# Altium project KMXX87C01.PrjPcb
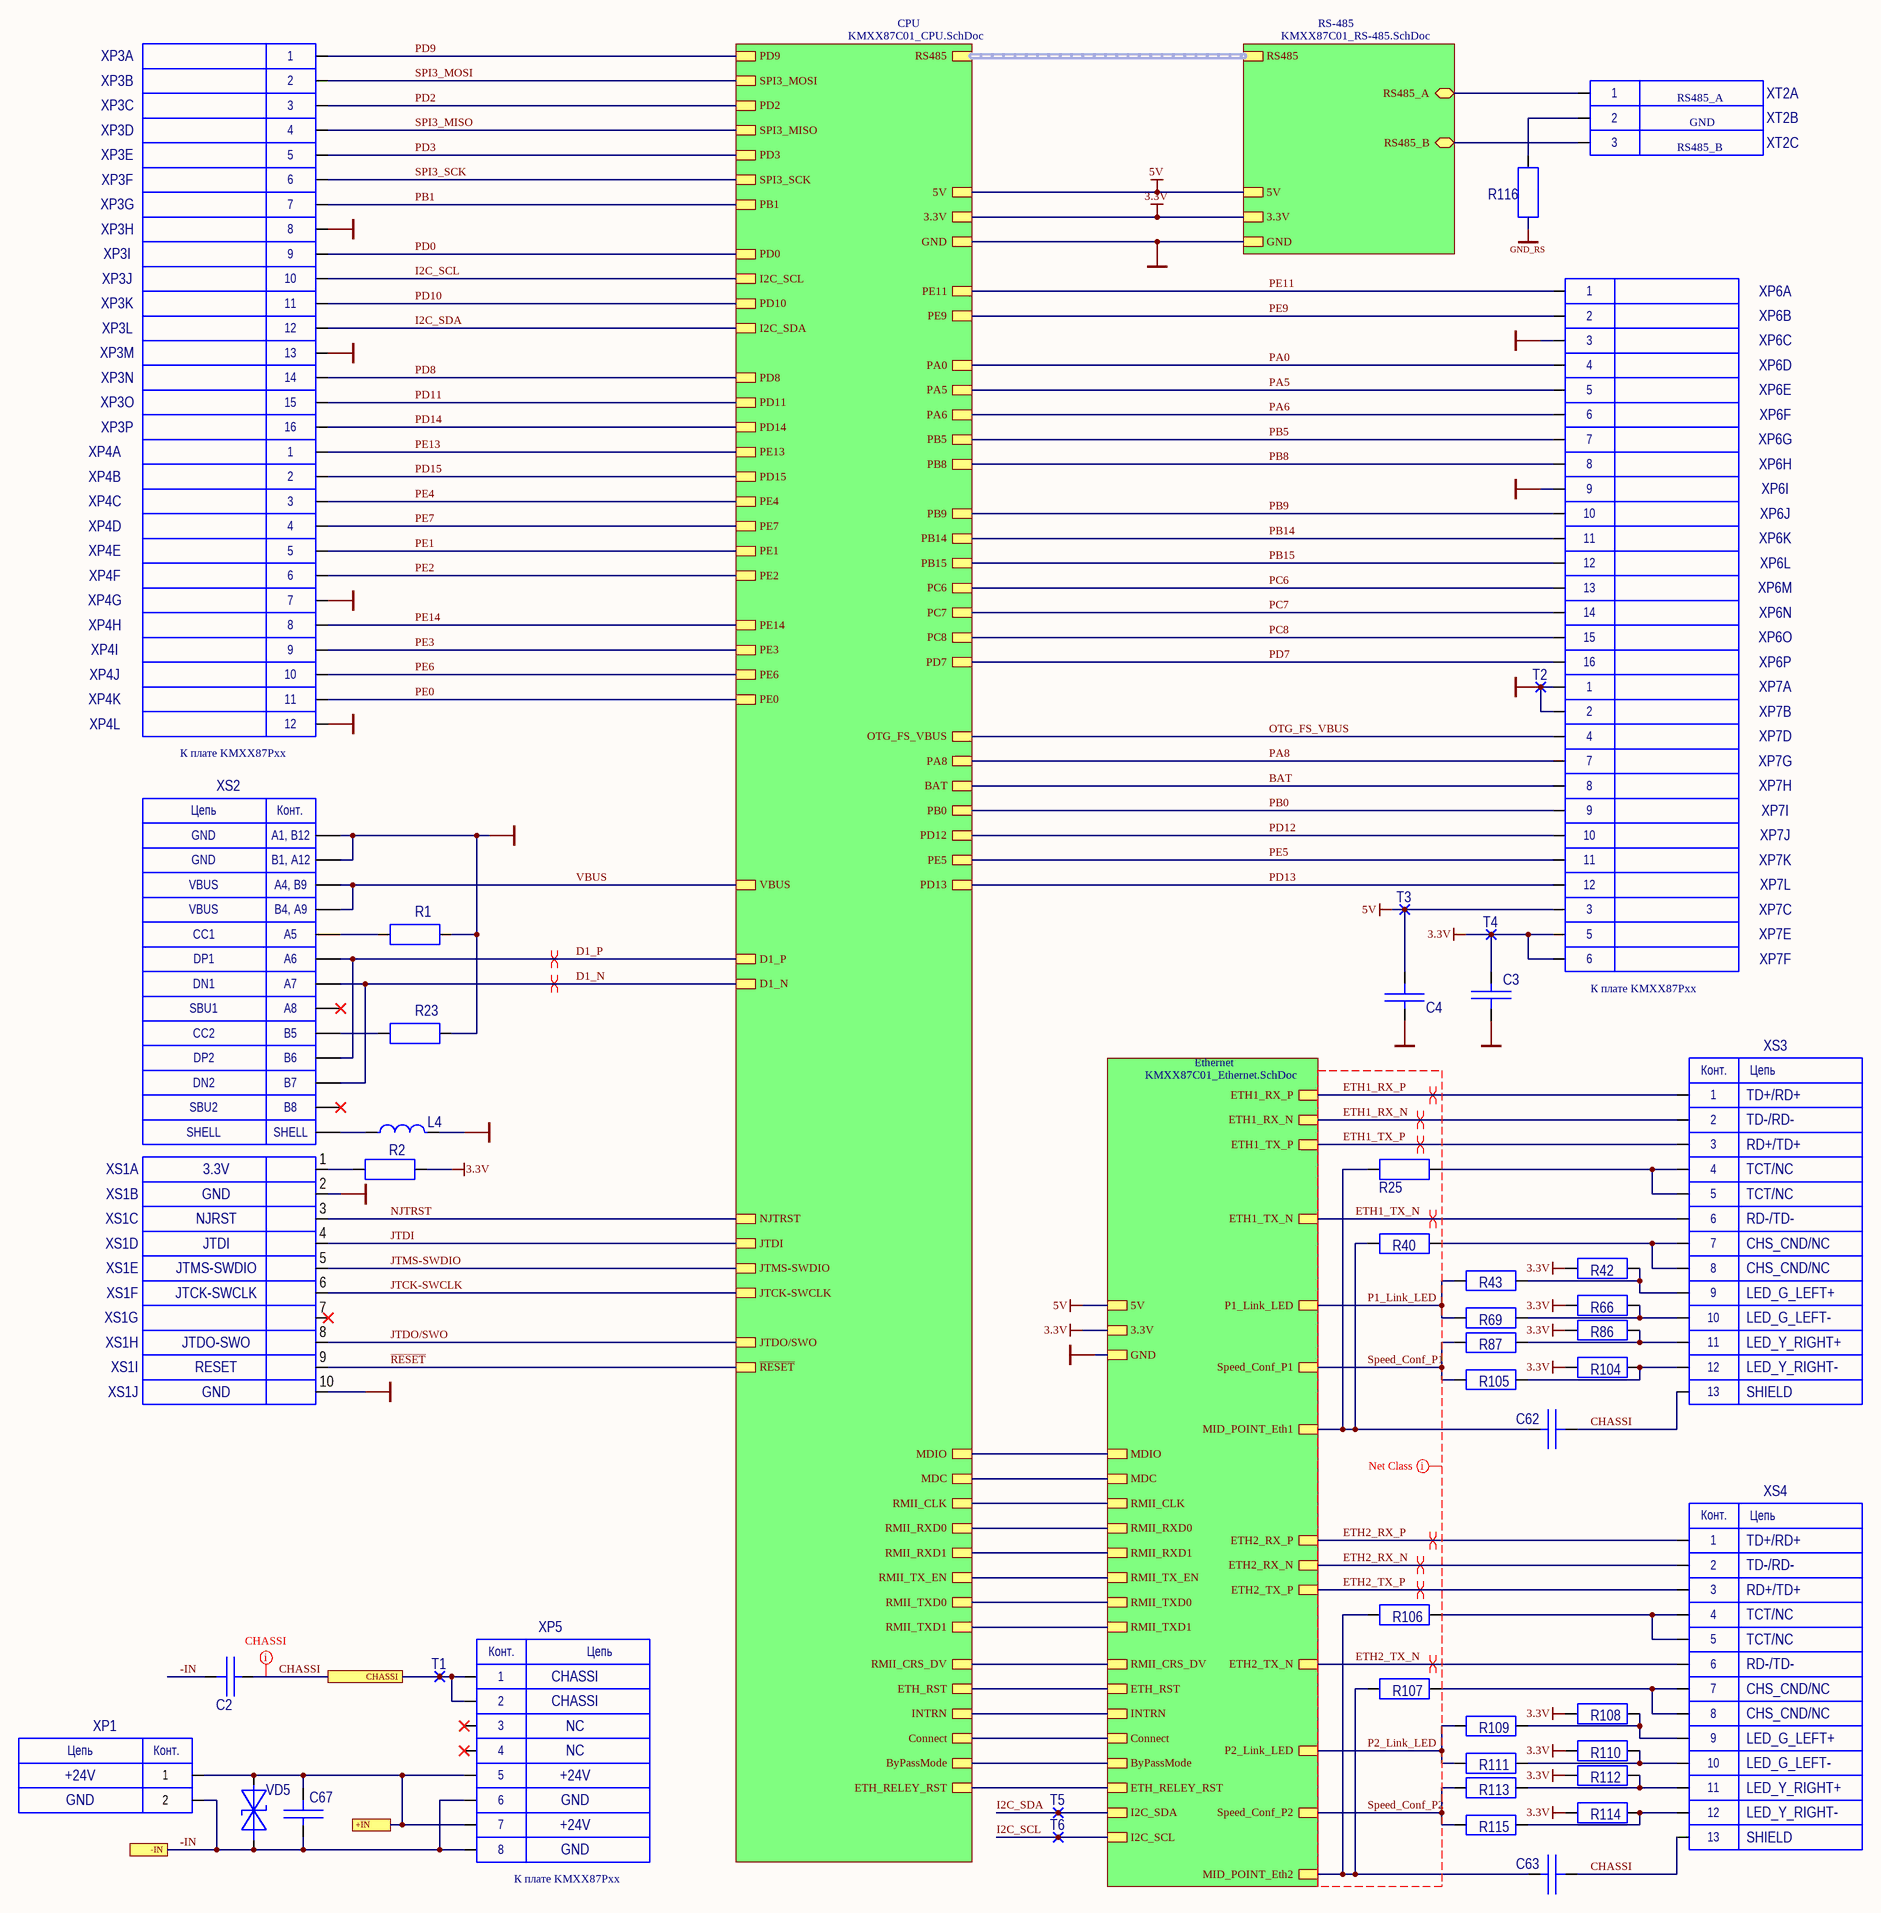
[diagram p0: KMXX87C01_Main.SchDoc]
4 sheets, 291 parts. Net scope: hierarchical (ports join the sheet entries above them; power ports are global).
Board file: KMXX87C01.PcbDoc
Sheets:
  KMXX87C01_Main.SchDoc
    CPU = KMXX87C01_CPU.SchDoc
    RS-485 = KMXX87C01_RS-485.SchDoc
    Ethernet = KMXX87C01_Ethernet.SchDoc

## Sheet KMXX87C01_Main.SchDoc
size 594 x 420 mm; SheetNumber: 1; SheetTotal: 4; Mass: not use; Title2: Схема электрическая принципиальная

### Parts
C2  CS-JY-Y2-1000пФ-20%-Y5U (Murata, 7.0x5.0x7.5)  [JY_8-A2]  (value not drawn)
C3  C0402-16В-0,1мкФ-10%-X7R (Walsin, 0402B104K160CT)  [C0402]  (value not drawn)
C4  C0402-16В-0,1мкФ-10%-X7R (Walsin, 0402B104K160CT)  [C0402]  (value not drawn)
C62  C1206-2000B-1000пФ-10%-X7R (Walsin, 1206B102K202CT  [CC1206-KL]  (value not drawn)
C63  C1206-2000B-1000пФ-10%-X7R (Walsin, 1206B102K202CT  [CC1206-KL]  (value not drawn)
C67  C1206-100В-0,1мкФ-10%-X7R (Samsung, CL31B104KCFNNN  [CC1206-KL]  (value not drawn)
L4  FB0805-5А-120 Ом (100МГц)-25%-0,02 Ом (INPAQ, MHC2012S121UBP)  [L0805]  (value not drawn)
R1  RC03-5,1кОм 1%  [RC0603-KL]  (value not drawn)
R2  RC02-0,0 Ом 5%  [R0402]  (value not drawn)
R23  RC03-5,1кОм 1%  [RC0603-KL]  (value not drawn)
R25  RC03-75 Ом 5%  [RC0603-KL]  (value not drawn)
R40  RC03-75 Ом 5%  [RC0603-KL]  (value not drawn)
R42  RC02-470 Ом 1%  [R0402]  (value not drawn)
R43  RC02-0,0 Ом 5%  [R0402]  (value not drawn)
R66  RC02-470 Ом 1%  [R0402]  (value not drawn)
R69  RC02-0,0 Ом 5%  [R0402]  (value not drawn)
R86  RC02-470 Ом 1%  [R0402]  (value not drawn)
R87  RC02-0,0 Ом 5%  [R0402]  (value not drawn)
R104  RC02-470 Ом 1%  [R0402]  (value not drawn)
R105  RC02-0,0 Ом 5%  [R0402]  (value not drawn)
R106  RC03-75 Ом 5%  [RC0603-KL]  (value not drawn)
R107  RC03-75 Ом 5%  [RC0603-KL]  (value not drawn)
R108  RC02-470 Ом 1%  [R0402]  (value not drawn)
R109  RC02-0,0 Ом 5%  [R0402]  (value not drawn)
R110  RC02-470 Ом 1%  [R0402]  (value not drawn)
R111  RC02-0,0 Ом 5%  [R0402]  (value not drawn)
R112  RC02-470 Ом 1%  [R0402]  (value not drawn)
R113  RC02-0,0 Ом 5%  [R0402]  (value not drawn)
R114  RC02-470 Ом 1%  [R0402]  (value not drawn)
R115  RC02-0,0 Ом 5%  [R0402]  (value not drawn)
R116  RC06-100 Ом 5%  [RC1206-KL]  (value not drawn)
T1  *  [T17A]  (value not drawn)  (no BOM)
T2  *  [T07A]  (value not drawn)  (no BOM)
T3  *  [T07A]  (value not drawn)  (no BOM)
T4  *  [T07A]  (value not drawn)  (no BOM)
T5  *  [T07A]  (value not drawn)  (no BOM)
T6  *  [T07A]  (value not drawn)  (no BOM)
VD5  SMBJ48CA-TR (STM, DO-214AA(SMB))  [SMB(DO-214AA)]  (value not drawn)
XP1  *  [2EDGR-5.08-02P]  (value not drawn)
XP3  PLD2-2 (Connfly,  DS1025-05-2*40P8BV1-B) (16 контактов)  [PLD2-16]  (value not drawn)  (parts A,B,C,D,E,F,G,H,I,J,K,L,M,N,O,P of 16)
XP4  *  [PLD2-12]  (value not drawn)  (parts A,B,C,D,E,F,G,H,I,J,K,L of 12)
XP5  *  [PLD2-08]  (value not drawn)
XP6  PLD2-2 (Connfly,  DS1025-05-2*40P8BV1-B) (16 контактов)  [PLD2-16]  (value not drawn)  (parts A,B,C,D,E,F,G,H,I,J,K,L,M,N,O,P of 16)
XP7  *  [PLD2-12]  (value not drawn)  (parts A,B,C,D,E,F,G,H,I,J,K,L of 12)
XS1  PBD1,27-2-5SM-G-4,5mm (Connfly, DS1065-05-2*5S8BSS  [PBD1.27-10S_small]  (value not drawn)  (parts A,B,C,D,E,F,G,H,I,J of 10)
XS2  *  [USB4105-GF-A-xxx]  (value not drawn)
XS3  MJ881B-B011-HLRVL11-P  [MJ881B-BX11-HRVL11-X]  (value not drawn)
XS4  MJ881B-B011-HLRVL11-P  [MJ881B-BX11-HRVL11-X]  (value not drawn)
XT2  *  [15EDGRC-3.5-03P]  (value not drawn)  (parts A,B,C of 3)

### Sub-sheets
CPU = KMXX87C01_CPU.SchDoc: RS485 (harness SPI3), GND, 3.3V, 5V, MDIO, MDC, RMII_CLK, RMII_RXD0, RMII_RXD1, RMII_TX_EN, RMII_TXD0, RMII_TXD1, RMII_CRS_DV, ETH_RST, INTRN, Connect, ByPassMode, ETH_RELEY_RST, NJTRST, JTDI, JTMS-SWDIO, JTCK-SWCLK, JTDO/SWO, ~{RESET}, PD2, D1_N, D1_P, VBUS, PD9, PD14, PD0, SPI3_MOSI, PE3, PD8, PD3, SPI3_MISO, SPI3_SCK, PB1, I2C_SDA, I2C_SCL, PE0, PD10, PE2, PE7, PD11, PE13, PD15, PE1, PE14, PE4, PE6, OTG_FS_VBUS, PE11, PE9, PA0, PA5, PA6, PB5, PB8, PB9, PB14, PB15, PC6, PC8, PD7, PC7, PA8, BAT, PB0, PD12, PD13, PE5
Ethernet = KMXX87C01_Ethernet.SchDoc: MDIO, MDC, RMII_CLK, RMII_RXD0, RMII_RXD1, RMII_TX_EN, RMII_TXD0, RMII_TXD1, RMII_CRS_DV, ETH_RST, INTRN, Connect, ByPassMode, ETH_RELEY_RST, I2C_SCL, I2C_SDA, 5V, 3.3V, GND, ETH2_RX_P, ETH2_RX_N, ETH2_TX_P, ETH2_TX_N, MID_POINT_Eth2, ETH1_RX_P, ETH1_RX_N, ETH1_TX_P, ETH1_TX_N, MID_POINT_Eth1, P1_Link_LED, Speed_Conf_P1, P2_Link_LED, Speed_Conf_P2
RS-485 = KMXX87C01_RS-485.SchDoc: RS485 (harness SPI3), GND, 3.3V, 5V, RS485_A (bidir), RS485_B (bidir)

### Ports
+IN, -IN, CHASSI

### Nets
3.3V: C3.1 R2.2 R42.1 R66.1 R86.1 R104.1 R108.1 R110.1 R112.1 R114.1 T4.1 XP7.5 XP7.6 ; sheet CPU/3.3V, sheet RS-485/3.3V, sheet Ethernet/3.3V
5V: C4.2 T3.1 XP7.3 ; sheet CPU/5V, sheet RS-485/5V, sheet Ethernet/5V
GND: C3.2 C4.1 L4.2 R1.2 R23.2 T2.1 XP3.8 XP3.13 XP4.7 XP4.12 XP6.3 XP6.9 XP7.1 XP7.2 XS1.2 XS1.10 XS2.A1_B12(GND) XS2.B1_A12(GND) ; sheet CPU/GND, sheet RS-485/GND, sheet Ethernet/GND
GND_RS: R116.1
-IN: C2.2 C67.1 VD5.2(K) XP1.2 XP5.6 XP5.8 ; port -IN
BAT: XP7.8 ; sheet CPU/BAT
ByPassMode: sheet CPU/ByPassMode, sheet Ethernet/ByPassMode
CHASSI: C2.1 C62.2 C63.2 T1.1 XP5.1 XP5.2 XS3.13(SHIELD) XS4.13(SHIELD) ; port CHASSI
Connect: sheet CPU/Connect, sheet Ethernet/Connect
D1_N: XS2.A7(DN1) XS2.B7(DN2) ; sheet CPU/D1_N
D1_P: XS2.A6(DP1) XS2.B6(DP2) ; sheet CPU/D1_P
ETH1_RX_N: XS3.2(TD-/RD-) ; sheet Ethernet/ETH1_RX_N
ETH1_RX_P: XS3.1(TD+/RD+) ; sheet Ethernet/ETH1_RX_P
ETH1_TX_N: XS3.6(RD-/TD-) ; sheet Ethernet/ETH1_TX_N
ETH1_TX_P: XS3.3(RD+/TD+) ; sheet Ethernet/ETH1_TX_P
ETH2_RX_N: XS4.2(TD-/RD-) ; sheet Ethernet/ETH2_RX_N
ETH2_RX_P: XS4.1(TD+/RD+) ; sheet Ethernet/ETH2_RX_P
ETH2_TX_N: XS4.6(RD-/TD-) ; sheet Ethernet/ETH2_TX_N
ETH2_TX_P: XS4.3(RD+/TD+) ; sheet Ethernet/ETH2_TX_P
ETH_RELEY_RST: sheet CPU/ETH_RELEY_RST, sheet Ethernet/ETH_RELEY_RST
ETH_RST: sheet CPU/ETH_RST, sheet Ethernet/ETH_RST
I2C_SCL: T6.1 XP3.10 ; sheet CPU/I2C_SCL, sheet Ethernet/I2C_SCL
I2C_SDA: T5.1 XP3.12 ; sheet CPU/I2C_SDA, sheet Ethernet/I2C_SDA
INTRN: sheet CPU/INTRN, sheet Ethernet/INTRN
JTCK-SWCLK: XS1.6 ; sheet CPU/JTCK-SWCLK
JTDI: XS1.4 ; sheet CPU/JTDI
JTDO/SWO: XS1.8 ; sheet CPU/JTDO/SWO
JTMS-SWDIO: XS1.5 ; sheet CPU/JTMS-SWDIO
MDC: sheet CPU/MDC, sheet Ethernet/MDC
MDIO: sheet CPU/MDIO, sheet Ethernet/MDIO
NJTRST: XS1.3 ; sheet CPU/NJTRST
OTG_FS_VBUS: XP7.4 ; sheet CPU/OTG_FS_VBUS
P1_Link_LED: R43.1 R69.1 ; sheet Ethernet/P1_Link_LED
P2_Link_LED: R109.1 R111.1 ; sheet Ethernet/P2_Link_LED
PA0: XP6.4 ; sheet CPU/PA0
PA5: XP6.5 ; sheet CPU/PA5
PA6: XP6.6 ; sheet CPU/PA6
PA8: XP7.7 ; sheet CPU/PA8
PB0: XP7.9 ; sheet CPU/PB0
PB1: XP3.7 ; sheet CPU/PB1
PB5: XP6.7 ; sheet CPU/PB5
PB8: XP6.8 ; sheet CPU/PB8
PB9: XP6.10 ; sheet CPU/PB9
PB14: XP6.11 ; sheet CPU/PB14
PB15: XP6.12 ; sheet CPU/PB15
PC6: XP6.13 ; sheet CPU/PC6
PC7: XP6.14 ; sheet CPU/PC7
PC8: XP6.15 ; sheet CPU/PC8
PD0: XP3.9 ; sheet CPU/PD0
PD2: XP3.3 ; sheet CPU/PD2
PD3: XP3.5 ; sheet CPU/PD3
PD7: XP6.16 ; sheet CPU/PD7
PD8: XP3.14 ; sheet CPU/PD8
PD9: XP3.1 ; sheet CPU/PD9
PD10: XP3.11 ; sheet CPU/PD10
PD11: XP3.15 ; sheet CPU/PD11
PD12: XP7.10 ; sheet CPU/PD12
PD13: XP7.12 ; sheet CPU/PD13
PD14: XP3.16 ; sheet CPU/PD14
PD15: XP4.2 ; sheet CPU/PD15
PE0: XP4.11 ; sheet CPU/PE0
PE1: XP4.5 ; sheet CPU/PE1
PE2: XP4.6 ; sheet CPU/PE2
PE3: XP4.9 ; sheet CPU/PE3
PE4: XP4.3 ; sheet CPU/PE4
PE5: XP7.11 ; sheet CPU/PE5
PE6: XP4.10 ; sheet CPU/PE6
PE7: XP4.4 ; sheet CPU/PE7
PE9: XP6.2 ; sheet CPU/PE9
PE11: XP6.1 ; sheet CPU/PE11
PE13: XP4.1 ; sheet CPU/PE13
PE14: XP4.8 ; sheet CPU/PE14
~{RESET}: XS1.9 ; sheet CPU/~{RESET}
RMII_CLK: sheet CPU/RMII_CLK, sheet Ethernet/RMII_CLK
RMII_CRS_DV: sheet CPU/RMII_CRS_DV, sheet Ethernet/RMII_CRS_DV
RMII_RXD0: sheet CPU/RMII_RXD0, sheet Ethernet/RMII_RXD0
RMII_RXD1: sheet CPU/RMII_RXD1, sheet Ethernet/RMII_RXD1
RMII_TX_EN: sheet CPU/RMII_TX_EN, sheet Ethernet/RMII_TX_EN
RMII_TXD0: sheet CPU/RMII_TXD0, sheet Ethernet/RMII_TXD0
RMII_TXD1: sheet CPU/RMII_TXD1, sheet Ethernet/RMII_TXD1
RS485_N: XT2.3 ; sheet RS-485/RS485_B
RS485_P: XT2.1 ; sheet RS-485/RS485_A
Speed_Conf_P1: R87.1 R105.1 ; sheet Ethernet/Speed_Conf_P1
Speed_Conf_P2: R113.1 R115.1 ; sheet Ethernet/Speed_Conf_P2
SPI3_MISO: XP3.4 ; sheet CPU/SPI3_MISO
SPI3_MOSI: XP3.2 ; sheet CPU/SPI3_MOSI
SPI3_SCK: XP3.6 ; sheet CPU/SPI3_SCK
VBUS: XS2.A4_B9(VBUS) XS2.B4_A9(VBUS) ; sheet CPU/VBUS
NetC62_1: C62.1 R25.1 R40.1 ; sheet Ethernet/MID_POINT_Eth1
NetC63_1: C63.1 R106.1 R107.1 ; sheet Ethernet/MID_POINT_Eth2
NetC67_2: C67.2 VD5.1(A) XP1.1 XP5.5 XP5.7 ; port +IN
NetL4_1: L4.1 XS2.SHELL(SHELL_GND)
NetR1_1: R1.1 XS2.A5(CC1)
NetR2_1: R2.1 XS1.1
NetR23_1: R23.1 XS2.B5(CC2)
NetR25_2: R25.2 XS3.4(TCT/NC) XS3.5(TCT/NC)
NetR40_2: R40.2 XS3.7(CHS_CND/NC) XS3.8(CHS_CND/NC)
NetR42_2: R42.2 R43.2 XS3.9(LED_G_LEFT+)
NetR66_2: R66.2 R69.2 XS3.10(LED_G_LEFT-)
NetR86_2: R86.2 R87.2 XS3.11(LED_Y_RIGHT+)
NetR104_2: R104.2 R105.2 XS3.12(LED_Y_RIGHT-)
NetR106_2: R106.2 XS4.4(TCT/NC) XS4.5(TCT/NC)
NetR107_2: R107.2 XS4.7(CHS_CND/NC) XS4.8(CHS_CND/NC)
NetR108_2: R108.2 R109.2 XS4.9(LED_G_LEFT+)
NetR110_2: R110.2 R111.2 XS4.10(LED_G_LEFT-)
NetR112_2: R112.2 R113.2 XS4.11(LED_Y_RIGHT+)
NetR114_2: R114.2 R115.2 XS4.12(LED_Y_RIGHT-)
NetR116_2: R116.2 XT2.2

Not connected (* = marked no-connect by the designer): XP5 3* 4*; XS1 7*; XS2 A8(SBU1)* B8(SBU2)*

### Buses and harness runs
harness sheet CPU/RS485 = sheet RS-485/RS485

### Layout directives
net class CHASSI: CHASSI
differential pair: D1_N, D1_P, ETH1_RX_N, ETH1_RX_P, ETH1_TX_N, ETH1_TX_P, ETH2_RX_N, ETH2_RX_P, ETH2_TX_N, ETH2_TX_P
net class Ethernet: ETH1_RX_N, ETH1_RX_P, ETH1_TX_N, ETH1_TX_P, ETH2_RX_N, ETH2_RX_P, ETH2_TX_N, ETH2_TX_P, P1_Link_LED, P2_Link_LED, Speed_Conf_P1, Speed_Conf_P2

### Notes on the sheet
- RS485_A
- RS485_B
- GND
- (near XP4) К плате KMXX87Pхх
- (near XP7) К плате KMXX87Pхх
- 3.3V
- NJRST
- JTDI
- JTMS-SWDIO
- JTCK-SWCLK
- JTDO-SWO
- RESET
- CHASSI
- NC
- +24V
- (near XP5) К плате KMXX87Pхх

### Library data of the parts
C2 = JY-8
C3 C4 = C0402
C62 C63 C67 = C1206
L4 = L0805
R1 R23 R25 R40 R106 R107 = RC03
R2 R42 R43 R66 R69 R86 R87 R104 R105 R108-R115 = R0402
R116 = RC06: Chip Resistor, 1206, Pmax=0.25W, Umax=200V, SIZE=3.2x1.6x0.6mm, SMT
T1 = T17A
T2-T6 = T07A
VD5 = P6KE7,5
XP1 = 2EDGR-5.08-02P
XP3 XP6 = PLD2-16: System: Connector
XP4 XP7 = PLD2-12_MULTI: Pin Header, Straight, Male, POS=12, ROW=2, PITCH=2.0mm, H=6.0mm, I=1.5A, U=125VAC, THT; Value2: DS1025-08-2*6 (Connfly); System: Connector
XP5 = PLD2-08: Pin Header, Straight, Male, POS=8, ROW=2, PITCH=2.0mm, H=6.0mm, I=1.5A, U=125VAC, THT; Value2: DS1025-05-2*4 (Connfly); System: Connector
XS1 = PBD1.27-10S
XS2 = USB4105-GF-A-xxx: USB-C (USB TYPE-C) USB 2.0 Receptacle Connector 24 (16+8 Dummy) Position Surface Mount, Right Angle; Through Hole
XS3 XS4 = MJ881B-BX11-HRVL11-X: RJ45 Offset Low Profile Connector, Latch - Tab UP, Magnetic - none
XT2 = 15EDGRC-3.5-03P_MULTI: Right angle, 3.5 mm pitch, 3 pins; Value2: (1803316) MC 1,5/ 6-G-3,81 - PCB header (Phoenix Contact)

## Sheet KMXX87C01_CPU.SchDoc
size 594 x 420 mm; SheetNumber: 2; SheetTotal: 4; Mass: not use; Title2: Схема электрическая принципиальная
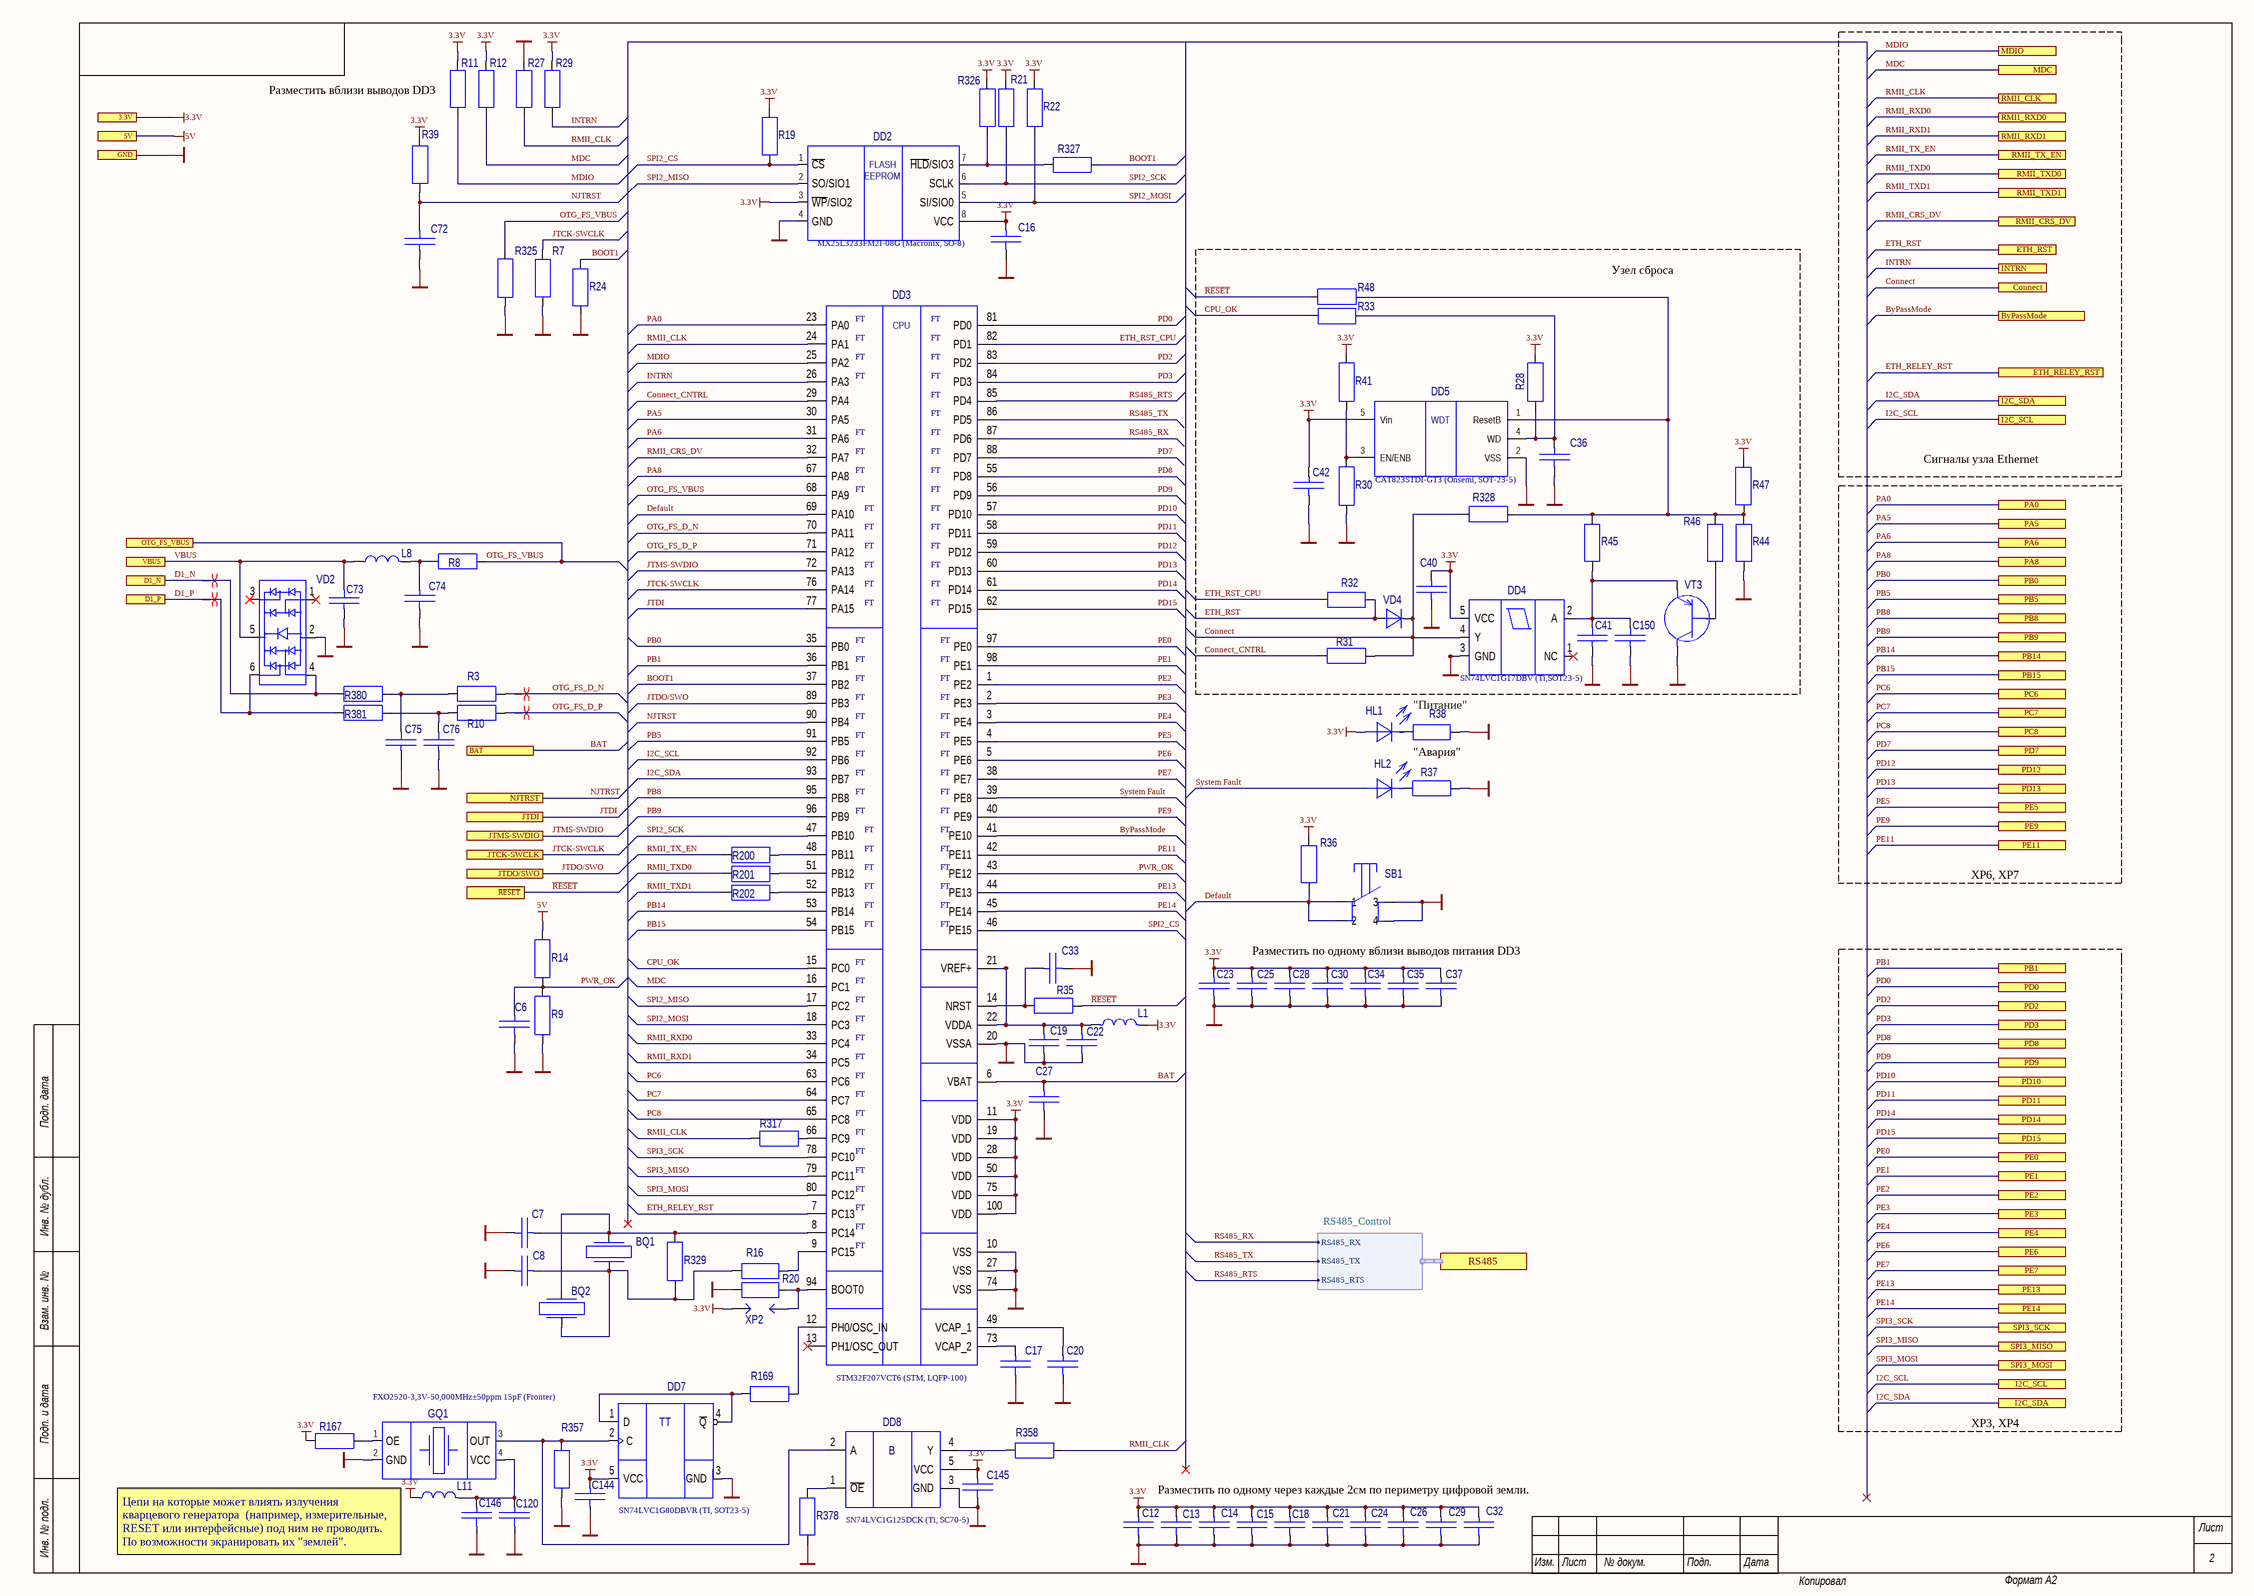
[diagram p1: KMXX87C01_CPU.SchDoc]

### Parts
BQ1  NX3215SA-32,768kHz±10ppm(25C)/±170ppm(-40/+85C)/6  [NX3215SA]  (value not drawn)
BQ2  MMTF32-32,768kHz±20ppm(25C)/±170ppm(-40/+85C)/6pF  [MMTF32]  (value not drawn)
C6  C0402-50В-0,01мкФ-10%-X7R (Walsin, 0402B103K500CT)  [C0402]  (value not drawn)
C7  C0603-50В-4,7пФ-0,25пФ-NPO (Walsin, 0603N4R7C500CT)  [CC0603-KL]  (value not drawn)
C8  C0603-50В-4,7пФ-0,25пФ-NPO (Walsin, 0603N4R7C500CT)  [CC0603-KL]  (value not drawn)
C12  C0402-50В-220пФ-5%-NPO (Walsin, 0402N221J500CT)  [C0402]  (value not drawn)
C13  C0402-50В-220пФ-5%-NPO (Walsin, 0402N221J500CT)  [C0402]  (value not drawn)
C14  C0402-50В-220пФ-5%-NPO (Walsin, 0402N221J500CT)  [C0402]  (value not drawn)
C15  C0402-50В-220пФ-5%-NPO (Walsin, 0402N221J500CT)  [C0402]  (value not drawn)
C16  C0402-16В-0,1мкФ-10%-X7R (Walsin, 0402B104K160CT)  [C0402]  (value not drawn)
C17  C0603-10В-2,2мкФ-10%-X7R (Samsung, CL10B225KP8NNNC  [CC0603-KL]  (value not drawn)
C18  C0402-50В-220пФ-5%-NPO (Walsin, 0402N221J500CT)  [C0402]  (value not drawn)
C19  C0402-50В-0,01мкФ-10%-X7R (Walsin, 0402B103K500CT)  [C0402]  (value not drawn)
C20  C0603-10В-2,2мкФ-10%-X7R (Samsung, CL10B225KP8NNNC  [CC0603-KL]  (value not drawn)
C21  C0402-50В-220пФ-5%-NPO (Walsin, 0402N221J500CT)  [C0402]  (value not drawn)
C22  C0603-25В-1,0мкФ-10%-X7R (Samsung, CL10B105KA8NNNC  [CC0603-KL]  (value not drawn)
C23  C0603-6,3В-4,7мкФ-10%-X5R (Samsung, CL10A475KQ8NNN  [CC0603-KL]  (value not drawn)
C24  C0402-50В-220пФ-5%-NPO (Walsin, 0402N221J500CT)  [C0402]  (value not drawn)
C25  C0402-16В-0,1мкФ-10%-X7R (Walsin, 0402B104K160CT)  [C0402]  (value not drawn)
C26  C0402-50В-220пФ-5%-NPO (Walsin, 0402N221J500CT)  [C0402]  (value not drawn)
C27  C0603-25В-1,0мкФ-10%-X7R (Samsung, CL10B105KA8NNNC  [CC0603-KL]  (value not drawn)
C28  C0402-16В-0,1мкФ-10%-X7R (Walsin, 0402B104K160CT)  [C0402]  (value not drawn)
C29  C0402-50В-220пФ-5%-NPO (Walsin, 0402N221J500CT)  [C0402]  (value not drawn)
C30  C0402-16В-0,1мкФ-10%-X7R (Walsin, 0402B104K160CT)  [C0402]  (value not drawn)
C32  C0402-50В-220пФ-5%-NPO (Walsin, 0402N221J500CT)  [C0402]  (value not drawn)
C33  C0402-50В-0,01мкФ-10%-X7R (Walsin, 0402B103K500CT)  [C0402]  (value not drawn)
C34  C0402-16В-0,1мкФ-10%-X7R (Walsin, 0402B104K160CT)  [C0402]  (value not drawn)
C35  C0402-16В-0,1мкФ-10%-X7R (Walsin, 0402B104K160CT)  [C0402]  (value not drawn)
C36  C0402-50В-0,01мкФ-10%-X7R (Walsin, 0402B103K500CT)  [C0402]  (value not drawn)
C37  C0402-16В-0,1мкФ-10%-X7R (Walsin, 0402B104K160CT)  [C0402]  (value not drawn)
C40  C0402-16В-0,1мкФ-10%-X7R (Walsin, 0402B104K160CT)  [C0402]  (value not drawn)
C41  C0805-16В-10мкФ-10%-X5R (Walsin, 0805X106K160CT)  [CC0805-KL]  (value not drawn)
C42  C0402-16В-0,1мкФ-10%-X7R (Walsin, 0402B104K160CT)  [C0402]  (value not drawn)
C72  C0402-50В-0,01мкФ-10%-X7R (Walsin, 0402B103K500CT)  [C0402]  (value not drawn)
C73  C0402-50В-0,01мкФ-10%-X7R (Walsin, 0402B103K500CT)  [C0402]  (value not drawn)
C74  C0402-16В-0,1мкФ-10%-X7R (Walsin, 0402B104K160CT)  [C0402]  (value not drawn)
C75  C0402-50В-33пФ-5%-NPO (Walsin, 0402N330J500CT)  [C0402]  (value not drawn)
C76  C0402-50В-33пФ-5%-NPO (Walsin, 0402N330J500CT)  [C0402]  (value not drawn)
C120  C0402-50В-0,01мкФ-10%-X7R (Walsin, 0402B103K500CT)  [C0402]  (value not drawn)
C144  C0402-16В-0,1мкФ-10%-X7R (Walsin, 0402B104K160CT)  [C0402]  (value not drawn)
C145  C0402-16В-0,1мкФ-10%-X7R (Walsin, 0402B104K160CT)  [C0402]  (value not drawn)
C146  C0603-10В-2,2мкФ-10%-X7R (Samsung, CL10B225KP8NNNC  [CC0603-KL]  (value not drawn)
C150  C0805-16В-10мкФ-10%-X5R (Walsin, 0805X106K160CT)  [CC0805-KL]  (value not drawn)
DD2  MX25L3233FM2I-08G (Macronix, SO-8)  [SOP127P790X216-8N]
DD3  STM32F207VCT6 (STM, LQFP-100)  [TSQFP50P1600X1600X160-100N]
DD4  SN74LVC1G17DBV (Ti,SOT23-5)  [SOT23-5]
DD5  CAT823STDI-GT3 (Onsemi, SOT-23-5)  [SOT23-5]
DD7  SN74LVC1G80DBVR (TI, SOT23-5)  [SOT23-5]
DD8  SN74LVC1G125DCK (Ti, SC70-5)  [SOT65P210-5N]
GQ1  FXO2520-3,3V-50,000MHz±50ppm 15pF (Fronter)  [FXO2520]
HL1  Name: "Питание"  [HT19-2132]  (hidden comment: HQ19-2132SYGC82 (HQG))
HL2  HT19-2132SURC-С  [HT19-2132]  (value not drawn)
L1  FB0603-0,2А-2500 Ом (100МГц)-25%-0,8 Ом (Viking)  [L0603]  (value not drawn)
L8  FB0805-5А-120 Ом (100МГц)-25%-0,02 Ом (INPAQ, MHC2012S121UBP)  [L0805]  (value not drawn)
L11  FB0603-0,2А-2500 Ом (100МГц)-25%-0,8 Ом (Viking)  [L0603]  (value not drawn)
R3  RC02-0,0 Ом 5%  [R0402]  (value not drawn)
R7  RC02-10кОм 1%  [R0402]  (value not drawn)
R8  RC02-0,0 Ом 5%  [R0402]  (value not drawn)
R9  RT03-6,65 кОм 1%-25ppm/C  [RC0603-KL]  (value not drawn)
R10  RC02-0,0 Ом 5%  [R0402]  (value not drawn)
R11  RC02-1,0кОм 1%  [R0402]  (value not drawn)
R12  RC02-1,0кОм 1%  [R0402]  (value not drawn)
R14  RT03-6,65 кОм 1%-25ppm/C  [RC0603-KL]  (value not drawn)
R16  RC02-0,0 Ом 5%  [R0402]  (value not drawn)
R19  RC02-10кОм 1%  [R0402]  (value not drawn)
R20  RC02-1,0кОм 1%  [R0402]  (value not drawn)
R21  RC02-10кОм 1%  [R0402]  (value not drawn)
R22  RC02-10кОм 1%  [R0402]  (value not drawn)
R24  RC02-4,7кОм 5%  [R0402]  (value not drawn)
R27  RC02-4,7кОм 5%  [R0402]  (value not drawn)
R28  RC02-10кОм 1%  [R0402]  (value not drawn)
R29  RC02-4,7кОм 5%  [R0402]  (value not drawn)
R30  Не устанавливать  [R0402]  (value not drawn)
R31  RC02-10кОм 1%  [R0402]  (value not drawn)
R32  RC02-200 Ом 5%  [R0402]  (value not drawn)
R33  RC02-200 Ом 5%  [R0402]  (value not drawn)
R35  RC02-1,0кОм 1%  [R0402]  (value not drawn)
R36  RC02-10кОм 1%  [R0402]  (value not drawn)
R37  RC02-1,0кОм 1%  [R0402]  (value not drawn)
R38  RC02-1,0кОм 1%  [R0402]  (value not drawn)
R39  RC02-4,7кОм 5%  [R0402]  (value not drawn)
R41  RC02-1,0кОм 1%  [R0402]  (value not drawn)
R44  RC02-100кОм 1%  [R0402]  (value not drawn)
R45  RC02-360кОм 1%  [R0402]  (value not drawn)
R46  RC02-200 Ом 5%  [R0402]  (value not drawn)
R47  Не устанавливать  [R0402]  (value not drawn)
R48  Не устанавливать  [R0402]  (value not drawn)
R167  Не устанавливать  [R0402]  (value not drawn)
R169  RC02-0,0 Ом 5%  [R0402]  (value not drawn)
R200  RC02-22 Ом-1%  [R0402]  (value not drawn)
R201  RC02-22 Ом-1%  [R0402]  (value not drawn)
R202  RC02-22 Ом-1%  [R0402]  (value not drawn)
R317  Не устанавливать  [R0402]  (value not drawn)
R325  RC02-1,0кОм 1%  [R0402]  (value not drawn)
R326  RC02-10кОм 1%  [R0402]  (value not drawn)
R327  RC02-0,0 Ом 5%  [R0402]  (value not drawn)
R328  Не устанавливать  [R0402]  (value not drawn)
R329  RC02-0,0 Ом 5%  [R0402]  (value not drawn)
R357  RC02-10кОм 1%  [R0402]  (value not drawn)
R358  RC02-22 Ом-1%  [R0402]  (value not drawn)
R378  RC02-0,0 Ом 5%  [R0402]  (value not drawn)
R380  RC02-22 Ом-1%  [R0402]  (value not drawn)
R381  RC02-22 Ом-1%  [R0402]  (value not drawn)
SB1  TP-1113S1-LR1325 (Tone Parts Electronics)  [TP-1113]  (value not drawn)
VD2  NUP4114UCLW1T2G (OnSemi, SC70)  [DCK]  (value not drawn)
VD4  Не устанавливать  [SOD323(VISHAY)]  (value not drawn)
VT3  BC807-40 (NXP, SOT-23)  [SOT-23A]  (value not drawn)
XP2  Не устанавливать  [JUMP1X2_2MM]  (value not drawn)

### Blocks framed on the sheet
Узел сброса: C36 C40-C42 C150 DD4 DD5 R28 R30-R33 R41 R44-R48 R328 VD4 VT3

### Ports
3.3V, 5V, BAT, ByPassMode, Connect, D1_N, D1_P, ETH_RELEY_RST, ETH_RST, GND, I2C_SCL, I2C_SDA, INTRN, JTCK-SWCLK, JTDI, JTDO/SWO, JTMS-SWDIO, MDC, MDIO, NJTRST, OTG_FS_VBUS, PA0, PA5, PA6, PA8, PB0, PB1, PB5, PB8, PB9, PB14, PB15, PC6, PC7, PC8, PD0, PD2, PD3, PD7, PD8, PD9, PD10, PD11, PD12, PD13, PD14, PD15, PE0, PE1, PE2, PE3, PE4, PE5, PE6, PE7, PE9, PE11, PE13, PE14, RMII_CLK, RMII_CRS_DV, RMII_RXD0, RMII_RXD1, RMII_TX_EN, RMII_TXD0, RMII_TXD1, RS485 (harness RS485_Control), SPI3_MISO, SPI3_MOSI, SPI3_SCK, VBUS, ~{RESET}

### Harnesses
RS485_Control: RS485_RX, RS485_TX, RS485_RTS

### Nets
3.3V: C12.1 C13.1 C14.1 C15.1 C16.1 C18.1 C21.1 C23.1 C24.1 C25.1 C26.1 C28.1 C29.1 C30.1 C32.1 C34.1 C35.1 C37.1 C40.1 C42.1 C144.1 C145.1 DD2.3(~{WP}/SIO2) DD2.8(VCC) DD3.11(VDD) DD3.19(VDD) DD3.28(VDD) DD3.50(VDD) DD3.75(VDD) DD3.100(VDD) DD4.5(VCC) DD5.5(Vin) DD7.5(VCC) DD8.5(VCC) HL1.A L1.2 L11.1 R11.2 R12.2 R19.2 R21.2 R22.2 R28.1 R29.2 R36.2 R39.2 R41.2 R47.1 R167.2 R326.2 XP2.1 ; port 3.3V
5V: R14.1 ; port 5V
GND: C6.2 C7.2 C8.2 C12.2 C13.2 C14.2 C15.2 C16.2 C17.2 C18.2 C19.2 C20.2 C21.2 C22.2 C23.2 C24.2 C25.2 C26.2 C27.2 C28.2 C29.2 C30.2 C32.2 C33.2 C34.2 C35.2 C36.2 C37.2 C40.2 C41.1 C42.2 C72.1 C73.1 C74.2 C75.1 C76.1 C120.2 C144.2 C145.2 C146.2 C150.1 DD2.4(GND) DD3.10(VSS) DD3.20(VSSA) DD3.27(VSS) DD3.74(VSS) DD4.3(GND) DD5.2(VSS) DD7.3(GND) DD8.3(GND) GQ1.2(GND) R7.1 R9.2 R20.2 R24.2 R27.2 R30.1 R37.2 R38.1 R44.1 R325.1 R357.1 R378.2 SB1.3 SB1.4 VD2.2 VT3.3(K) ; port GND
BAT: C27.1 DD3.6(VBAT) ; port BAT
BOOT1: DD3.37(PB2) R24.1 R327.1
ByPassMode: DD3.41(PE10) ; port ByPassMode
Connect: DD4.4(Y) R31.2 R328.1 VD4.2(C) ; port Connect
Connect_CNTRL: DD3.29(PA4) R31.1
CPU_OK: DD3.15(PC0) R33.2
D1_N: R380.1 VD2.4 ; port D1_N
D1_P: R381.1 VD2.6 ; port D1_P
Default: DD3.69(PA10) R36.1 SB1.1 SB1.2
ETH_RELEY_RST: DD3.7(PC13) ; port ETH_RELEY_RST
ETH_RST: R32.1 VD4.1(A) ; port ETH_RST
ETH_RST_CPU: DD3.82(PD1) R32.2
I2C_SCL: DD3.92(PB6) ; port I2C_SCL
I2C_SDA: DD3.93(PB7) ; port I2C_SDA
INTRN: DD3.26(PA3) R29.1 ; port INTRN
JTCK-SWCLK: DD3.76(PA14) R7.2 ; port JTCK-SWCLK
JTDI: DD3.77(PA15) ; port JTDI
JTDO/SWO: DD3.89(PB3) ; port JTDO/SWO
JTMS-SWDIO: DD3.72(PA13) ; port JTMS-SWDIO
MDC: DD3.16(PC1) R12.1 ; port MDC
MDIO: DD3.25(PA2) R11.1 ; port MDIO
NJTRST: C72.2 DD3.90(PB4) R39.1 ; port NJTRST
OTG_FS_D_N: DD3.70(PA11) R3.2
OTG_FS_D_P: DD3.71(PA12) R10.2
OTG_FS_VBUS: DD3.68(PA9) R8.2 R325.2 ; port OTG_FS_VBUS
PA0: DD3.23(PA0) ; port PA0
PA5: DD3.30(PA5) ; port PA5
PA6: DD3.31(PA6) ; port PA6
PA8: DD3.67(PA8) ; port PA8
PB0: DD3.35(PB0) ; port PB0
PB1: DD3.36(PB1) ; port PB1
PB5: DD3.91(PB5) ; port PB5
PB8: DD3.95(PB8) ; port PB8
PB9: DD3.96(PB9) ; port PB9
PB14: DD3.53(PB14) ; port PB14
PB15: DD3.54(PB15) ; port PB15
PC6: DD3.63(PC6) ; port PC6
PC7: DD3.64(PC7) ; port PC7
PC8: DD3.65(PC8) ; port PC8
PD0: DD3.81(PD0) ; port PD0
PD2: DD3.83(PD2) ; port PD2
PD3: DD3.84(PD3) ; port PD3
PD7: DD3.88(PD7) ; port PD7
PD8: DD3.55(PD8) ; port PD8
PD9: DD3.56(PD9) ; port PD9
PD10: DD3.57(PD10) ; port PD10
PD11: DD3.58(PD11) ; port PD11
PD12: DD3.59(PD12) ; port PD12
PD13: DD3.60(PD13) ; port PD13
PD14: DD3.61(PD14) ; port PD14
PD15: DD3.62(PD15) ; port PD15
PE0: DD3.97(PE0) ; port PE0
PE1: DD3.98(PE1) ; port PE1
PE2: DD3.1(PE2) ; port PE2
PE3: DD3.2(PE3) ; port PE3
PE4: DD3.3(PE4) ; port PE4
PE5: DD3.4(PE5) ; port PE5
PE6: DD3.5(PE6) ; port PE6
PE7: DD3.38(PE7) ; port PE7
PE9: DD3.40(PE9) ; port PE9
PE11: DD3.42(PE11) ; port PE11
PE13: DD3.44(PE13) ; port PE13
PE14: DD3.45(PE14) ; port PE14
PWR_OK: C6.1 DD3.43(PE12) R9.1 R14.2
~{RESET}: R35.2 R48.1 ; port ~{RESET}
RMII_CLK: DD3.24(PA1) R27.1 R317.2 R358.1 ; port RMII_CLK
RMII_CRS_DV: DD3.32(PA7) ; port RMII_CRS_DV
RMII_RXD0: DD3.33(PC4) ; port RMII_RXD0
RMII_RXD1: DD3.34(PC5) ; port RMII_RXD1
RMII_TX_EN: R200.2 ; port RMII_TX_EN
RMII_TXD0: R201.2 ; port RMII_TXD0
RMII_TXD1: R202.2 ; port RMII_TXD1
RS485_RTS: DD3.85(PD4) ; port RS485.RS485_RTS
RS485_RX: DD3.87(PD6) ; port RS485.RS485_RX
RS485_TX: DD3.86(PD5) ; port RS485.RS485_TX
SPI2_CS: DD2.1(~{CS}) DD3.46(PE15) R19.1
SPI2_MISO: DD2.2(SO/SIO1) DD3.17(PC2)
SPI2_MOSI: DD2.5(SI/SIO0) DD3.18(PC3) R22.1
SPI2_SCK: DD2.6(SCLK) DD3.47(PB10) R21.1
SPI3_MISO: DD3.79(PC11) ; port SPI3_MISO
SPI3_MOSI: DD3.80(PC12) ; port SPI3_MOSI
SPI3_SCK: DD3.78(PC10) ; port SPI3_SCK
System Fault: DD3.39(PE8) HL2.A
VBUS: C73.2 L8.1 VD2.5 ; port VBUS
NetBQ1_1: BQ1.1 BQ2.2 C8.1 R16.2 R329.2
NetBQ1_2: BQ1.2 BQ2.1 C7.1 DD3.8(PC14) R329.1
NetC17_1: C17.1 DD3.73(VCAP_2)
NetC19_1: C19.1 C22.1 DD3.21(VREF+) DD3.22(VDDA) L1.1
NetC20_1: C20.1 DD3.49(VCAP_1)
NetC33_1: C33.1 DD3.14(NRST) R35.1
NetC36_1: C36.1 DD5.4(WD) R28.2 R33.1
NetC41_2: C41.2 C150.2 DD4.2(A) R45.2 VT3.2(E)
NetC74_1: C74.1 L8.2 R8.1
NetC75_2: C75.2 R3.1 R380.2
NetC76_2: C76.2 R10.1 R381.2
NetC120_1: C120.1 C146.1 GQ1.4(VCC) L11.2
NetDD2_7: DD2.7(~{HLD}/SIO3) R326.1 R327.2
NetDD3_9: DD3.9(PC15) R16.1
NetDD3_12: DD3.12(PH0/OSC_IN) R169.1
NetDD3_48: DD3.48(PB11) R200.1
NetDD3_51: DD3.51(PB12) R201.1
NetDD3_52: DD3.52(PB13) R202.1
NetDD3_66: DD3.66(PC9) R317.1
NetDD3_94: DD3.94(BOOT0) R20.1 XP2.2
NetDD5_1: DD5.1(ResetB) R44.2 R45.1 R46.1 R47.2 R48.2 R328.2
NetDD5_3: DD5.3(EN/ENB) R30.2 R41.1
NetDD7_1: DD7.1(D) DD7.4(~{Q}) R169.2
NetDD7_2: DD7.2(C) DD8.2(A) GQ1.3(OUT) R357.2
NetDD8_1: DD8.1(~{OE}) R378.1
NetDD8_4: DD8.4(Y) R358.2
NetGQ1_1: GQ1.1(OE) R167.1
NetHL1_C: HL1.C R38.2
NetHL2_C: HL2.C R37.1
NetR46_2: R46.2 VT3.1(B)

Not connected (* = marked no-connect by the designer): DD3 13(PH1/OSC_OUT)* 99(RFU); DD4 1(NC)*; SB1 5 6; VD2 1* 3*

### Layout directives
differential pair: D1_N, D1_P, OTG_FS_D_N, OTG_FS_D_P

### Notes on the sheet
- (near R11) Разместить вблизи выводов DD3
- (near DD3) FT
- Сигналы узла Ethernet
- "Авария"
- XP6, XP7
- Разместить по одному вблизи выводов питания DD3
- XP3, XP4
- Разместить по одному через каждые 2см по периметру цифровой земли.
- Цепи на которые может влиять излучения кварцевого генератора  (например, измерительные, RESET или интерфейсные) под ним не проводить. По возможности экранировать их "землей".

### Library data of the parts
BQ1 = NX3215SA
BQ2 = MMTF32
C6 C12-C16 C18 C19 C21 C24-C26 C28-C30 C32-C37 C40 C42 C72-C76 C120 C144 C145 = C0402
C7 C8 C17 C20 C22 C23 C27 C146 = C0603
C41 C150 = C0805
DD2 = MX25L6433FM2I-08G: EEPROM Flash Memory, NOR, Serial SPI/QSPI Interface, f=80/133MHz, 64-Mbit, Vcc=2.7V...3.6V, SOIC-8 (200mil). SMT
DD3 = STM32F207VCT6: ARM-based 32-bit MCU with 256KB Flash; Alternative: STM32F207VET6; Alternative2: GD32F207VCT6; Alternative3: GD32F207VET6
DD4 = SN74LVC1G17DBV
DD5 = XC6121-24: Voltage Detector with Watchdog Function and ON/OFF Control
DD7 = SN74LVC1G80DBV: Single Positiive Edge Triggered D-Type Flip-Flop
DD8 = SN74LVC1G125DCK: Buffer / line driver
GQ1 = FXO2520: SMD Crystal Oscillator 2.5x2.0, 2.0-50.0 MHz, 3.3V; Value2: DSO221SHF; Value3: NZ2520SB
HL1 HL2 = HT19-2132SYGC: High Brigh Yellow-Green LED
L1 L11 = L0603
L8 = L0805
R3 R7 R8 R10-R12 R19-R22 R24 R27-R33 R35-R39 R41 R44-R47 R169 R200-R202 R326 R327 R357 R358 R378 R380 R381 = R0402
R9 R14 R16 R325 R329 = RC03
R48 = R0402: Value2: RC02-1,0кОм 5%
R167 = RC03: Value2: RC02-0,0 Ом 5%
R317 R328 = R0402: Value2: RC02-0,0 Ом 5%
SB1 = TP-1113: Dicription: 6.0*4.0 Horizontal Mini SMD Tact Switch   TP-1113
VD2 = TPD4E001DCKR: 4-Channel ESD Protection Array with 1.5pF IO Cap.
VD4 = BAS16WS: Value2: BAS16HT1G (ON, SOD-323)
VT3 = BC807-25
XP2 = JUMP1X2_2MM

## Sheet KMXX87C01_RS-485.SchDoc
size 420 x 297 mm; SheetNumber: 4; SheetTotal: 4; Mass: not use; Title2: Схема электрическая принципиальная
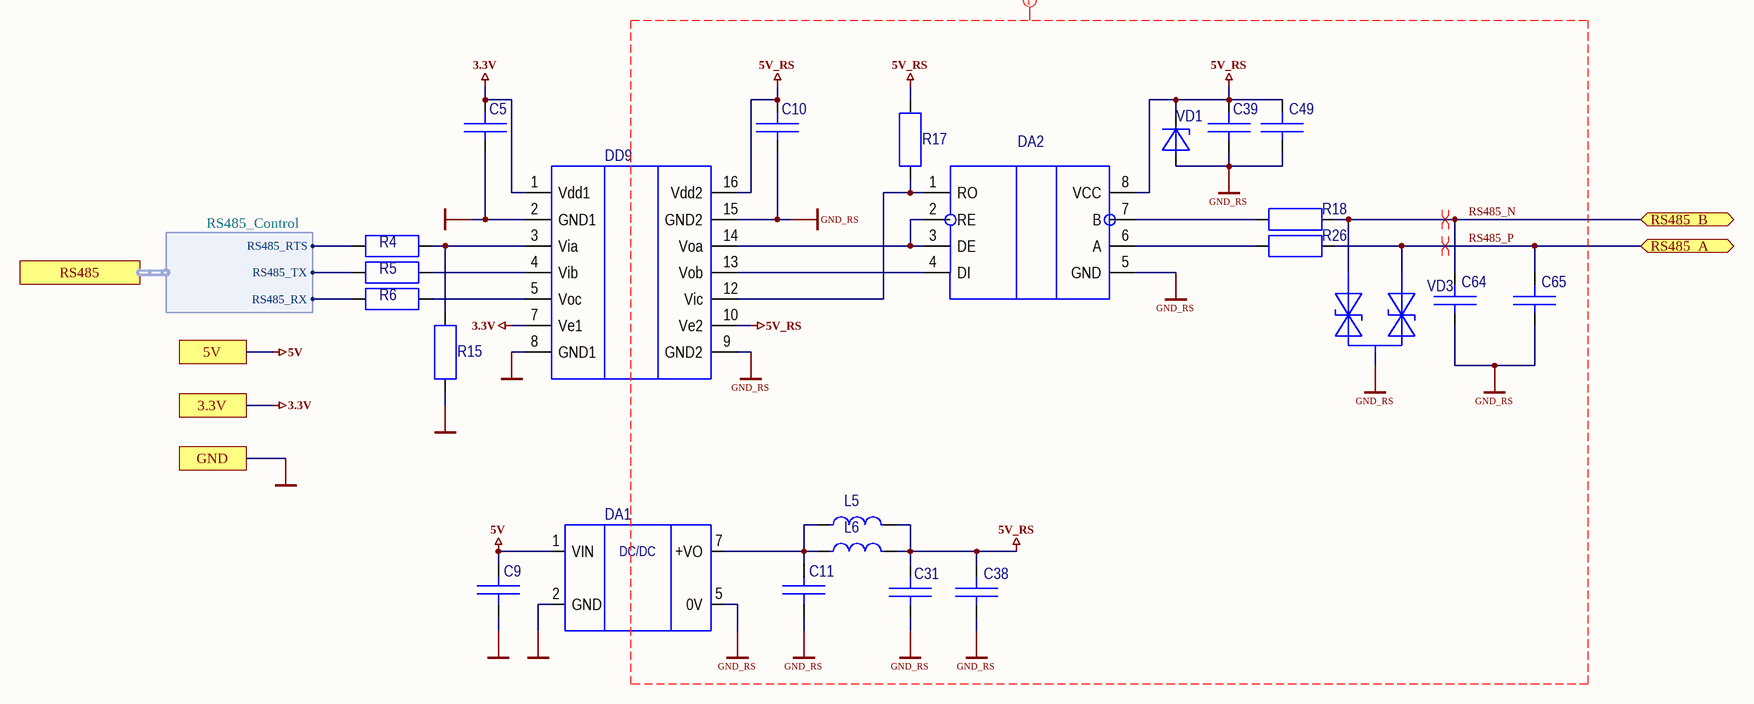
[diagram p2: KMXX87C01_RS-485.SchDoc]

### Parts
C5  C0402-16В-0,1мкФ-10%-X7R (Samsung, CL05B104KO5NNNC  [C0402]  (value not drawn)
C9  C0603-25В-1,0мкФ-10%-X7R (Samsung, CL10B105KA8NNNC  [CC0603-KL]  (value not drawn)
C10  C0402-16В-0,1мкФ-10%-X7R (Samsung, CL05B104KO5NNNC  [C0402]  (value not drawn)
C11  C0603-25В-1,0мкФ-10%-X7R (Samsung, CL10B105KA8NNNC  [CC0603-KL]  (value not drawn)
C31  C0402-16В-0,1мкФ-10%-X7R (Samsung, CL05B104KO5NNNC  [C0402]  (value not drawn)
C38  C1206-16В-10мкФ-10%-X7R (Samsung, CL31B106KOHNNNE)  [CC1206-KL]  (value not drawn)
C39  C0402-16В-0,1мкФ-10%-X7R (Samsung, CL05B104KO5NNNC  [C0402]  (value not drawn)
C49  C1206-16В-10мкФ-10%-X7R (Samsung, CL31B106KOHNNNE)  [CC1206-KL]  (value not drawn)
C64  Не устанавливать  [CC0603-KL]  (value not drawn)  (no BOM)
C65  Не устанавливать  [CC0603-KL]  (value not drawn)  (no BOM)
DA1  F0505S-1WR2  [F0505S-1W]  (value not drawn)
DA2  THVD1500DR (TI, SO-8)  [SO8]  (value not drawn)
DD9  ISO7331CDWR (TI, SO_W-16)  [SO-16_W]  (value not drawn)
L5  FB0805-1,5А-120 Ом (100МГц)-25%-0,03 Ом (Murata, B  [L0805]  (value not drawn)
L6  1.0uH  [L1206]  (value not drawn)  (no BOM)
R4  RC02-10 Ом 5%  [R0402]  (value not drawn)
R5  RC02-10 Ом 5%  [R0402]  (value not drawn)
R6  RC02-10 Ом 5%  [R0402]  (value not drawn)
R15  RC02-10кОм 1%  [R0402]  (value not drawn)
R17  RC02-10кОм 1%  [R0402]  (value not drawn)
R18  RC03-10 Ом 5%  [RC0603-KL]  (value not drawn)
R26  RC03-10 Ом 5%  [RC0603-KL]  (value not drawn)
VD1  SMBJ6.5A  [SMB(DO-214AA)]  (value not drawn)
VD3  SM712-02HTG  [SOT-23]  (value not drawn)

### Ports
3.3V, 5V, GND, RS485 (harness RS485_Control), RS485_A (bidir), RS485_B (bidir)

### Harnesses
RS485_Control: RS485_RTS, RS485_TX, RS485_RX

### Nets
3.3V: C5.2 DD9.1(Vdd1) DD9.7(Ve1) ; port 3.3V
5V: C9.1 DA1.1(VIN) ; port 5V
5V_RS: C10.2 C31.2 C38.2 C39.2 C49.2 DA2.8(VCC) DD9.10(Ve2) DD9.16(Vdd2) L5.2 L6.2 R17.2 VD1.2(K)
GND: C5.1 C9.2 DA1.2(GND) DD9.2(GND1) DD9.8(GND1) R15.1 ; port GND
GND_RS: C10.1 C11.2 C31.1 C38.1 C39.1 C49.1 C64.1 C65.1 DA1.5(0V) DA2.5(GND) DD9.9(GND2) DD9.15(GND2) VD1.1(A) VD3.3
RS485_N: C64.2 R18.1 VD3.2 ; port RS485_B
RS485_P: C65.2 R26.1 VD3.1 ; port RS485_A
RS485_RTS: R4.1 ; port RS485.RS485_RTS
RS485_RX: R6.1 ; port RS485.RS485_RX
RS485_TX: R5.1 ; port RS485.RS485_TX
NetC11_1: C11.1 DA1.7(+VO) L5.1 L6.1
NetDA2_1: DA2.1(RO) DD9.12(Vic) R17.1
NetDA2_2: DA2.2(RE) DA2.3(DE) DD9.14(Voa)
NetDA2_4: DA2.4(DI) DD9.13(Vob)
NetDA2_6: DA2.6(A) R26.2
NetDA2_7: DA2.7(B) R18.2
NetDD9_3: DD9.3(Via) R4.2 R15.2
NetDD9_4: DD9.4(Vib) R5.2
NetDD9_5: DD9.5(Voc) R6.2

Not connected (* = marked no-connect by the designer): DD9 6 11

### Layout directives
differential pair: RS485_N, RS485_P
net class RS485: 5V_RS, GND_RS, RS485_N, RS485_P

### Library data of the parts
C5 C10 C31 C39 = C0402
C9 C11 = C0603
C38 C49 = C1206
C64 C65 = C0603: Value2: C0603-50В-100пФ-5%-NPO
DA1 = F0505S-1W: Value: F0505S-1WR2 (Mornsun, SIP-5)
DA2 = ADM485AR
DD9 = ADUM1301
L5 = L0805
L6 = L1206: Inductor, 1206, 1uH, 1200mA, 0.15Ohm; Value2: L1206-1,0мкГн-20% (MURATA, LQM31); Value: Не устанавливать
R4-R6 R15 R17 = R0402
R18 R26 = RC03
VD1 = SMBJ6.5: SM6T27A
VD3 = SM712: 600W, Asymmetrical TVS Diode Array; Value: SM712-02HTG (Littelfuse, SOT23-3)

## Sheet KMXX87C01_Ethernet.SchDoc
size 594 x 420 mm; CompanyName: not use; DrawnBy: Харыбин В.; Engineer: not use; Organization: not use; Address1: not use; Address2: not use; Address3: not use; Address4: not use; Revision: not use; SheetNumber: 3; Mass: not use; Title2: Схема электрическая принципиальная
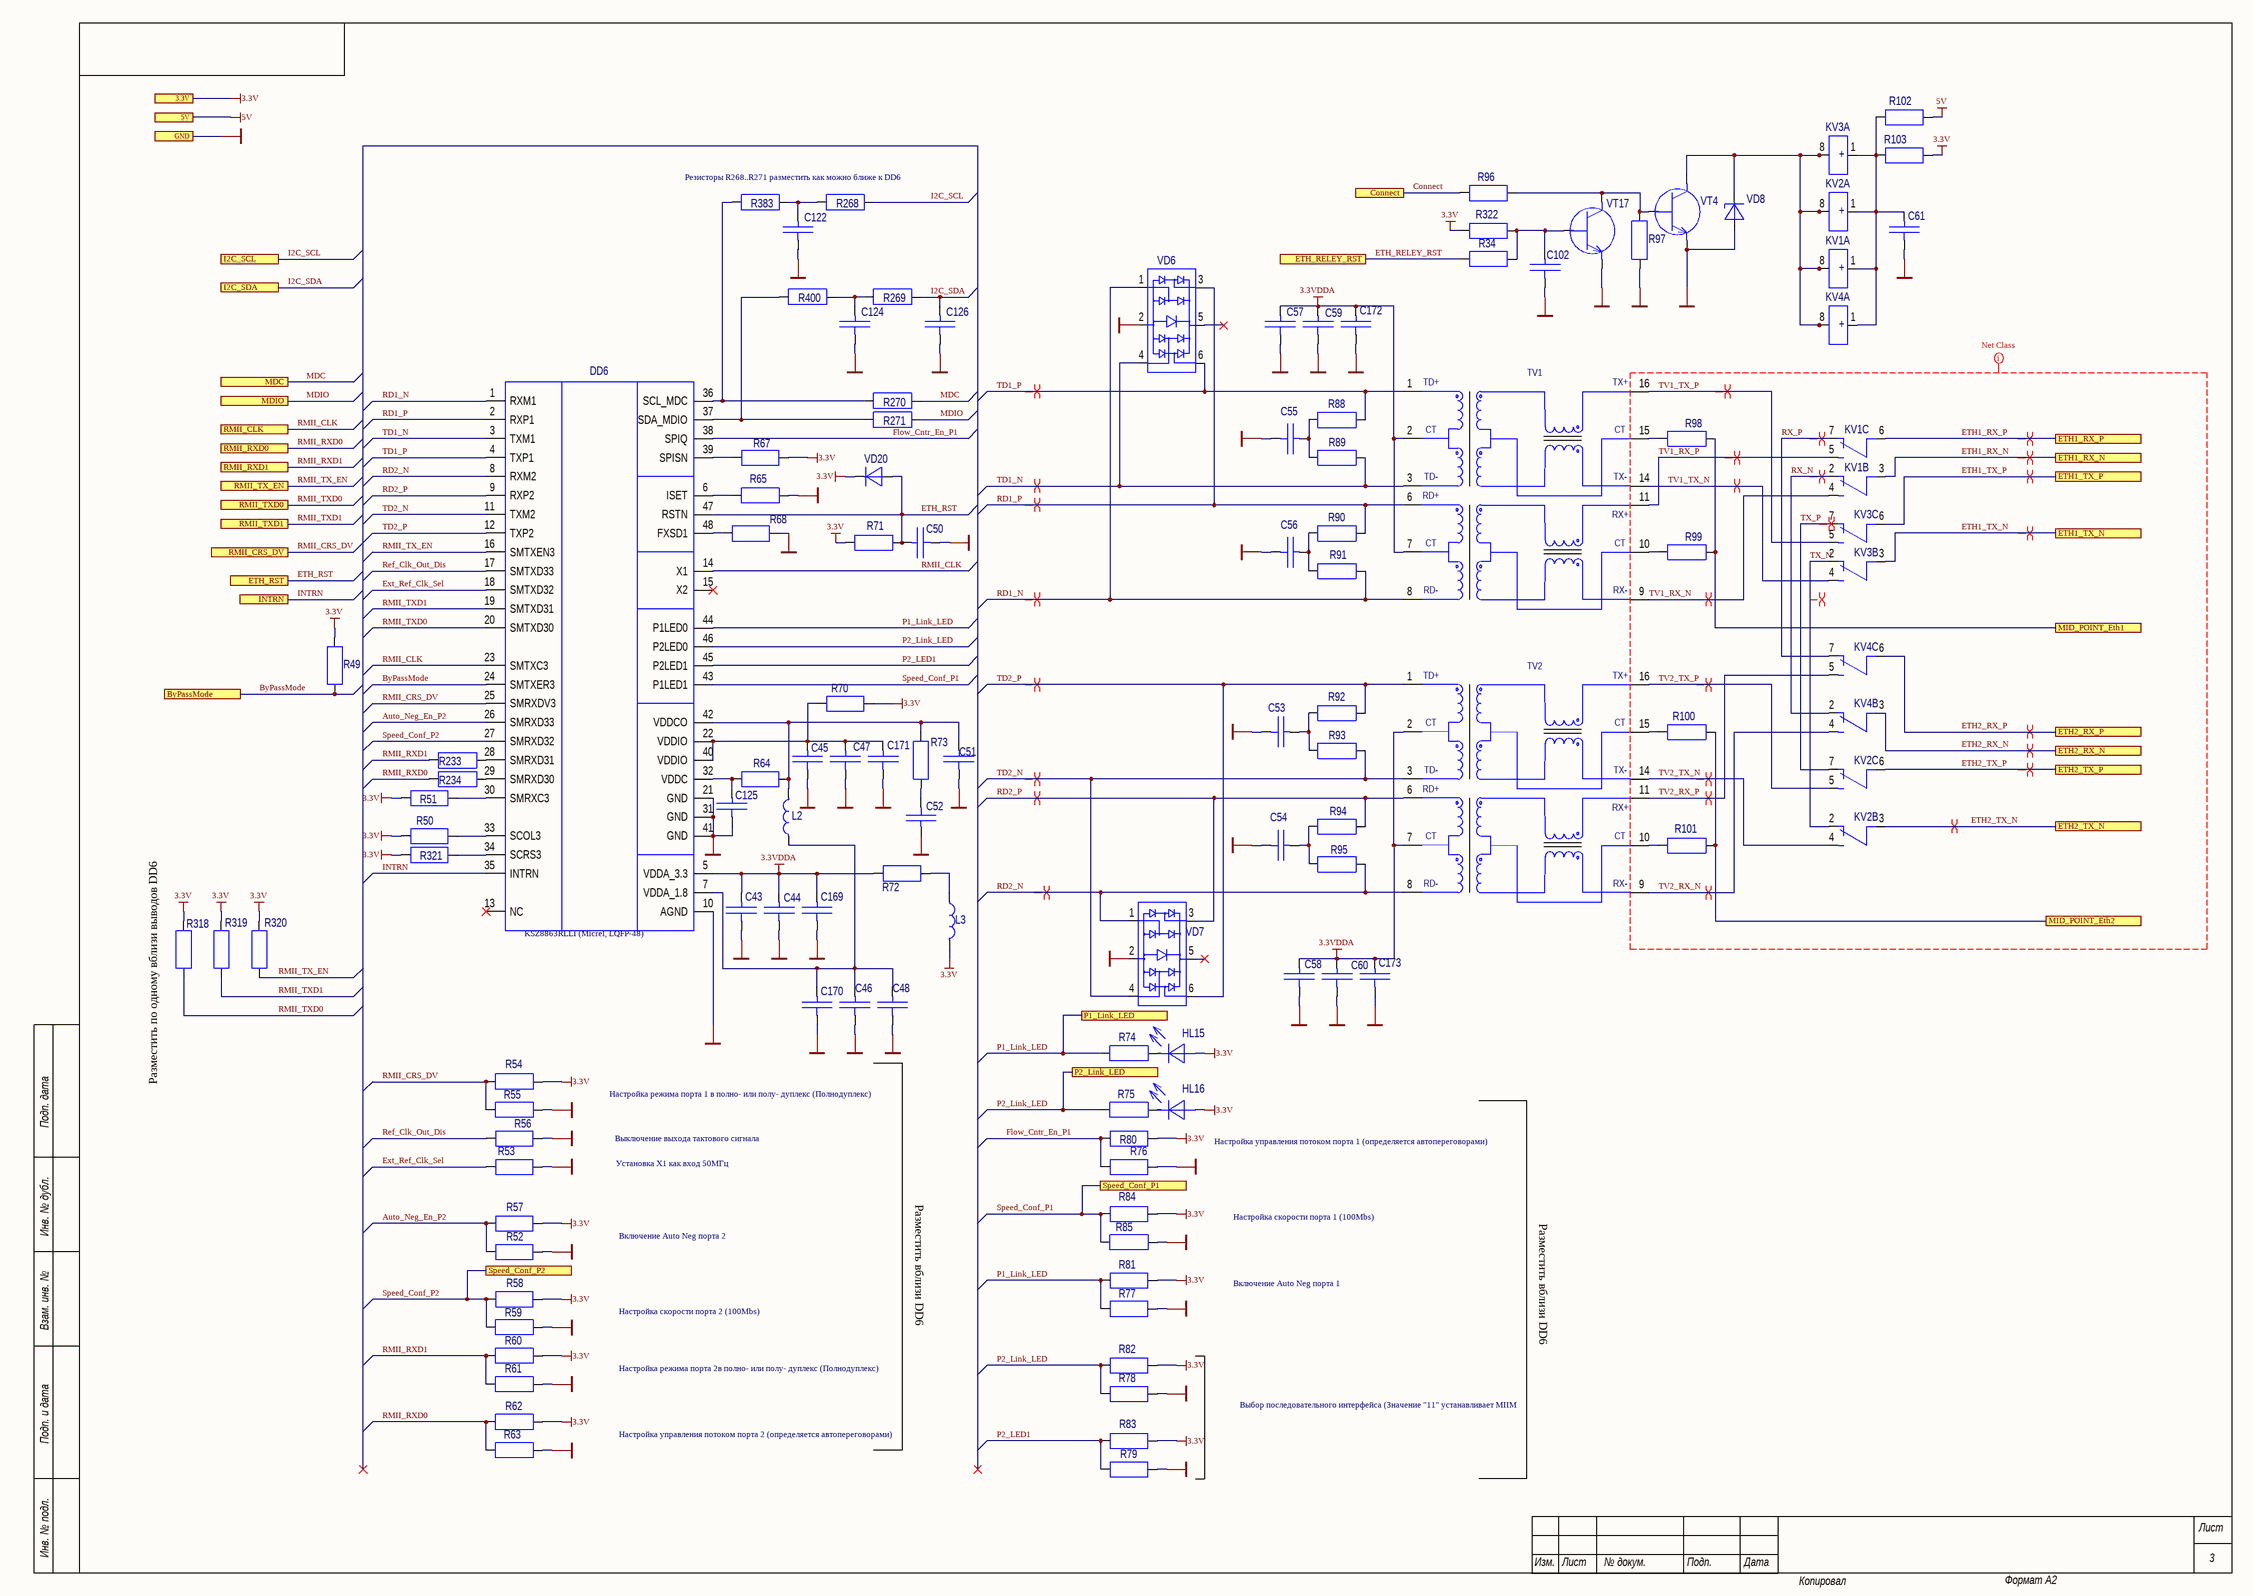
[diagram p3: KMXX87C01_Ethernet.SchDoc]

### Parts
C43  C0603-25В-1,0мкФ-10%-X7R (Samsung, CL10B105KA8NNNC  [CC0603-KL]  (value not drawn)
C44  C0402-16В-0,1мкФ-10%-X7R (Walsin, 0402B104K160CT)  [C0402]  (value not drawn)
C45  C0402-16В-0,1мкФ-10%-X7R (Walsin, 0402B104K160CT)  [C0402]  (value not drawn)
C46  C0603-25В-1,0мкФ-10%-X7R (Samsung, CL10B105KA8NNNC  [CC0603-KL]  (value not drawn)
C47  C0402-16В-0,1мкФ-10%-X7R (Walsin, 0402B104K160CT)  [C0402]  (value not drawn)
C48  C0402-16В-0,1мкФ-10%-X7R (Walsin, 0402B104K160CT)  [C0402]  (value not drawn)
C50  C0402-50В-0,01мкФ-10%-X7R (Walsin, 0402B103K500CT)  [C0402]  (value not drawn)
C51  C0402-16В-0,1мкФ-10%-X7R (Walsin, 0402B104K160CT)  [C0402]  (value not drawn)
C52  C0805-16В-10мкФ-10%-X5R (Walsin, 0805X106K160CT)  [CC0805-KL]  (value not drawn)
C53  C0402-16В-0,1мкФ-10%-X7R (Walsin, 0402B104K160CT)  [C0402]  (value not drawn)
C54  C0402-16В-0,1мкФ-10%-X7R (Walsin, 0402B104K160CT)  [C0402]  (value not drawn)
C55  C0402-16В-0,1мкФ-10%-X7R (Walsin, 0402B104K160CT)  [C0402]  (value not drawn)
C56  C0402-16В-0,1мкФ-10%-X7R (Walsin, 0402B104K160CT)  [C0402]  (value not drawn)
C57  C0402-16В-0,1мкФ-10%-X7R (Walsin, 0402B104K160CT)  [C0402]  (value not drawn)
C58  C0402-16В-0,1мкФ-10%-X7R (Walsin, 0402B104K160CT)  [C0402]  (value not drawn)
C59  C0402-16В-0,1мкФ-10%-X7R (Walsin, 0402B104K160CT)  [C0402]  (value not drawn)
C60  C0402-16В-0,1мкФ-10%-X7R (Walsin, 0402B104K160CT)  [C0402]  (value not drawn)
C61  C0603-25В-1,0мкФ-10%-X7R (Samsung, CL10B105KA8NNNC  [CC0603-KL]  (value not drawn)
C102  C0603-25В-1,0мкФ-10%-X7R (Samsung, CL10B105KA8NNNC  [CC0603-KL]  (value not drawn)
C122  C0402-50В-10пФ-5%-NPO (Murata, GRM1555C1H100JA01D)  [C0402]  (value not drawn)
C124  C0402-50В-10пФ-5%-NPO (Murata, GRM1555C1H100JA01D)  [C0402]  (value not drawn)
C125  C0402-16В-0,1мкФ-10%-X7R (Walsin, 0402B104K160CT)  [C0402]  (value not drawn)
C126  C0402-16В-0,1мкФ-10%-X7R (Walsin, 0402B104K160CT)  [C0402]  (value not drawn)
C169  C0603-10В-10мкф-10%-X5R (Samsung, CL10A106KP8NNNC)  [CC0603-KL]  (value not drawn)
C170  C0603-10В-10мкф-10%-X5R (Samsung, CL10A106KP8NNNC)  [CC0603-KL]  (value not drawn)
C171  C0603-10В-10мкф-10%-X5R (Samsung, CL10A106KP8NNNC)  [CC0603-KL]  (value not drawn)
C172  C0603-10В-10мкф-10%-X5R (Samsung, CL10A106KP8NNNC)  [CC0603-KL]  (value not drawn)
C173  C0603-10В-10мкф-10%-X5R (Samsung, CL10A106KP8NNNC)  [CC0603-KL]  (value not drawn)
DD6  KSZ8863RLLI (Micrel, LQFP-48)  [TSQFP50P900X900X160-48N]
HL15  HQ19-2132SYGC82 (HQG)  [HT19-2132]  (value not drawn)
HL16  HQ19-2132SYGC82 (HQG)  [HT19-2132]  (value not drawn)
KV1  HFD4/5-SR (Hongfa)  [TE IM03GR Gul wings]  (value not drawn)  (parts A,B,C of 3)
KV2  HFD4/5-SR (Hongfa)  [TE IM03GR Gul wings]  (value not drawn)  (parts A,B,C of 3)
KV3  HFD4/5-SR (Hongfa)  [TE IM03GR Gul wings]  (value not drawn)  (parts A,B,C of 3)
KV4  HFD4/5-SR (Hongfa)  [TE IM03GR Gul wings]  (value not drawn)  (parts A,B,C of 3)
L2  FB0603-0,2А-2500 Ом (100МГц)-25%-0,8 Ом (Viking)  [L0603]  (value not drawn)
L3  FB0603-0,2А-2500 Ом (100МГц)-25%-0,8 Ом (Viking)  [L0603]  (value not drawn)
R34  RC02-200 Ом 5%  [R0402]  (value not drawn)
R49  RC02-4,7кОм 5%  [R0402]  (value not drawn)
R50  RC02-4,7кОм 5%  [R0402]  (value not drawn)
R51  RC02-4,7кОм 5%  [R0402]  (value not drawn)
R52  Не устанавливать  [R0402]  (value not drawn)
R53  RC02-1,0кОм 1%  [R0402]  (value not drawn)
R54  RC02-4,7кОм 5%  [R0402]  (value not drawn)
R55  Не устанавливать  [R0402]  (value not drawn)
R56  RC02-1,0кОм 1%  [R0402]  (value not drawn)
R57  RC02-4,7кОм 5%  [R0402]  (value not drawn)
R58  RC02-4,7кОм 5%  [R0402]  (value not drawn)
R59  Не устанавливать  [R0402]  (value not drawn)
R60  RC02-4,7кОм 5%  [R0402]  (value not drawn)
R61  Не устанавливать  [R0402]  (value not drawn)
R62  Не устанавливать  [R0402]  (value not drawn)
R63  RC02-1,0кОм 1%  [R0402]  (value not drawn)
R64  RC02-0,0 Ом 5%  [R0402]  (value not drawn)
R65  RC02-11,8кОм 1%  [R0402]  (value not drawn)
R67  RC02-4,7кОм 5%  [R0402]  (value not drawn)
R68  RC02-1,0кОм 1%  [R0402]  (value not drawn)
R70  RC02-0,0 Ом 5%  [R0402]  (value not drawn)
R71  RC02-100кОм 1%  [R0402]  (value not drawn)
R72  RC02-0,0 Ом 5%  [R0402]  (value not drawn)
R73  RC02-0,0 Ом 5%  [R0402]  (value not drawn)
R74  RC02-470 Ом 1%  [R0402]  (value not drawn)
R75  RC02-470 Ом 1%  [R0402]  (value not drawn)
R76  RC02-1,0кОм 1%  [R0402]  (value not drawn)
R77  Не устанавливать  [R0402]  (value not drawn)
R78  Не устанавливать  [R0402]  (value not drawn)
R79  RC02-1,0кОм 1%  [R0402]  (value not drawn)
R80  Не устанавливать  [R0402]  (value not drawn)
R81  RC02-4,7кОм 5%  [R0402]  (value not drawn)
R82  RC02-4,7кОм 5%  [R0402]  (value not drawn)
R83  RC02-4,7кОм 5%  [R0402]  (value not drawn)
R84  RC02-4,7кОм 5%  [R0402]  (value not drawn)
R85  Не устанавливать  [R0402]  (value not drawn)
R88  RC02-49,9 Ом 1%  [R0402]  (value not drawn)
R89  RC02-49,9 Ом 1%  [R0402]  (value not drawn)
R90  RC02-49,9 Ом 1%  [R0402]  (value not drawn)
R91  RC02-49,9 Ом 1%  [R0402]  (value not drawn)
R92  RC02-49,9 Ом 1%  [R0402]  (value not drawn)
R93  RC02-49,9 Ом 1%  [R0402]  (value not drawn)
R94  RC02-49,9 Ом 1%  [R0402]  (value not drawn)
R95  RC02-49,9 Ом 1%  [R0402]  (value not drawn)
R96  RC02-1,0кОм 1%  [R0402]  (value not drawn)
R97  RC02-4,7кОм 5%  [R0402]  (value not drawn)
R98  RC03-75 Ом 5%  [RC0603-KL]  (value not drawn)
R99  RC03-75 Ом 5%  [RC0603-KL]  (value not drawn)
R100  RC03-75 Ом 5%  [RC0603-KL]  (value not drawn)
R101  RC03-75 Ом 5%  [RC0603-KL]  (value not drawn)
R102  RC02-0,0 Ом 5%  [R0402]  (value not drawn)
R103  Не устанавливать  [R0402]  (value not drawn)
R233  RC02-22 Ом-1%  [R0402]  (value not drawn)
R234  RC02-22 Ом-1%  [R0402]  (value not drawn)
R268  RC02-100 Ом 5%  [R0402]  (value not drawn)
R269  RC02-100 Ом 5%  [R0402]  (value not drawn)
R270  RC02-0,0 Ом 5%  [R0402]  (value not drawn)
R271  RC02-0,0 Ом 5%  [R0402]  (value not drawn)
R318  RC02-4,7кОм 5%  [R0402]  (value not drawn)
R319  RC02-4,7кОм 5%  [R0402]  (value not drawn)
R320  RC02-4,7кОм 5%  [R0402]  (value not drawn)
R321  RC02-4,7кОм 5%  [R0402]  (value not drawn)
R322  RC02-4,7кОм 5%  [R0402]  (value not drawn)
R383  RC02-0,0 Ом 5%  [R0402]  (value not drawn)
R400  RC02-0,0 Ом 5%  [R0402]  (value not drawn)
TV1  *  [PT61018PEL]  (value not drawn)
TV2  *  [PT61018PEL]  (value not drawn)
VD6  NUP4114UCLW1T2G (OnSemi, SC70)  [DCK]  (value not drawn)
VD7  NUP4114UCLW1T2G (OnSemi, SC70)  [DCK]  (value not drawn)
VD8  BZV55C36 (NXP, SOD80C)  [DL-35]  (value not drawn)
VD20  BAS716 (NXP, SOD-523)  [SOD-523]  (value not drawn)
VT4  BC817-40L (ONSemi, SOT-23)  [SOT-23A]  (value not drawn)
VT17  BC817-40L (ONSemi, SOT-23)  [SOT-23A]  (value not drawn)

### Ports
3.3V, 5V, ByPassMode, Connect, ETH1_RX_N, ETH1_RX_P, ETH1_TX_N, ETH1_TX_P, ETH2_RX_N, ETH2_RX_P, ETH2_TX_N, ETH2_TX_P, ETH_RELEY_RST, ETH_RST, GND, I2C_SCL, I2C_SDA, INTRN, MDC, MDIO, MID_POINT_Eth1, MID_POINT_Eth2, P1_Link_LED, P2_Link_LED, RMII_CLK, RMII_CRS_DV, RMII_RXD0, RMII_RXD1, RMII_TX_EN, RMII_TXD0, RMII_TXD1, Speed_Conf_P1, Speed_Conf_P2

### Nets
3.3V: HL15.A HL16.A L3.2 R49.2 R50.2 R51.2 R54.2 R57.1 R58.1 R60.2 R62.2 R67.1 R70.1 R71.2 R80.1 R81.1 R82.1 R83.1 R84.1 R103.1 R318.2 R319.2 R320.2 R321.2 R322.2 VD20.2(C) ; port 3.3V
3.3VDDA: C43.1 C44.1 C57.1 C58.1 C59.1 C60.1 C169.1 C172.1 C173.1 DD6.5(VDDA_3.3) R72.1 TV1.2(CT) TV1.7(CT) TV2.2(CT) TV2.7(CT)
5V: R102.1 ; port 5V
GND: C43.2 C44.2 C45.2 C46.2 C47.2 C48.2 C50.2 C51.2 C52.1 C53.2 C54.2 C55.2 C56.2 C57.2 C58.2 C59.2 C60.2 C61.2 C102.2 C122.2 C124.2 C125.2 C126.2 C169.2 C170.2 C171.2 C172.2 C173.2 DD6.10(AGND) DD6.21(GND) DD6.31(GND) DD6.41(GND) R52.1 R53.1 R55.2 R56.1 R59.2 R61.2 R63.2 R65.2 R68.1 R76.1 R77.1 R78.1 R79.1 R85.2 R97.2 VD6.2 VD7.2 VD8.1(A) VT4.2(E) VT17.2(E) ; port GND
Auto_Neg_En_P2: DD6.26(SMRXD33) R52.2 R57.2
ByPassMode: DD6.24(SMTXER3) R49.1 ; port ByPassMode
Connect: R96.2 ; port Connect
ETH1_RX_N: KV1.3 ; port ETH1_RX_N
ETH1_RX_P: KV1.6 ; port ETH1_RX_P
ETH1_TX_N: KV3.3 ; port ETH1_TX_N
ETH1_TX_P: KV3.6 ; port ETH1_TX_P
ETH2_RX_N: KV4.3 ; port ETH2_RX_N
ETH2_RX_P: KV4.6 ; port ETH2_RX_P
ETH2_TX_N: KV2.3 ; port ETH2_TX_N
ETH2_TX_P: KV2.6 ; port ETH2_TX_P
ETH_RELEY_RST: R34.1 ; port ETH_RELEY_RST
ETH_RST: C50.1 DD6.47(RSTN) R71.1 VD20.1(A) ; port ETH_RST
Ext_Ref_Clk_Sel: DD6.18(SMTXD32) R53.2
Flow_Cntr_En_P1: DD6.38(SPIQ) R76.2 R80.2
I2C_SCL: R268.2 ; port I2C_SCL
I2C_SDA: C126.1 R269.2 ; port I2C_SDA
INTRN: DD6.35(INTRN) ; port INTRN
MDC: R270.2 ; port MDC
MDIO: R271.2 ; port MDIO
P1_Link_LED: DD6.44(P1LED0) R74.1 R77.2 R81.2 ; port P1_Link_LED
P2_LED1: DD6.45(P2LED1) R79.2 R83.2
P2_Link_LED: DD6.46(P2LED0) R75.1 R78.2 R82.2 ; port P2_Link_LED
RD1_N: DD6.1(RXM1) R91.1 TV1.8(RD-) VD6.1
RD1_P: DD6.2(RXP1) R90.1 TV1.6(RD+) VD6.3
RD2_N: DD6.8(RXM2) R95.1 TV2.8(RD-) VD7.1
RD2_P: DD6.9(RXP2) R94.1 TV2.6(RD+) VD7.3
Ref_Clk_Out_Dis: DD6.17(SMTXD33) R56.2
RMII_CLK: DD6.14(X1) DD6.23(SMTXC3) ; port RMII_CLK
RMII_CRS_DV: DD6.25(SMRXDV3) R54.1 R55.1 ; port RMII_CRS_DV
RMII_RXD0: R62.1 R63.1 R234.2 ; port RMII_RXD0
RMII_RXD1: R60.1 R61.1 R233.2 ; port RMII_RXD1
RMII_TX_EN: DD6.16(SMTXEN3) R320.1 ; port RMII_TX_EN
RMII_TXD0: DD6.20(SMTXD30) R318.1 ; port RMII_TXD0
RMII_TXD1: DD6.19(SMTXD31) R319.1 ; port RMII_TXD1
RX_N: KV1.2 KV4.2
RX_P: KV1.7 KV4.7
Speed_Conf_P1: DD6.43(P1LED1) R84.2 R85.1 ; port Speed_Conf_P1
Speed_Conf_P2: DD6.27(SMRXD32) R58.2 R59.1 ; port Speed_Conf_P2
TD1_N: DD6.3(TXM1) R89.1 TV1.3(TD-) VD6.4
TD1_P: DD6.4(TXP1) R88.1 TV1.1(TD+) VD6.6
TD2_N: DD6.11(TXM2) R93.1 TV2.3(TD-) VD7.4
TD2_P: DD6.12(TXP2) R92.1 TV2.1(TD+) VD7.6
TV1_RX_N: KV1.4 TV1.9(RX-)
TV1_RX_P: KV1.5 TV1.11(RX+)
TV1_TX_N: KV3.4 TV1.14(TX-)
TV1_TX_P: KV3.5 TV1.16(TX+)
TV2_RX_N: KV4.4 TV2.9(RX-)
TV2_RX_P: KV4.5 TV2.11(RX+)
TV2_TX_N: KV2.4 TV2.14(TX-)
TV2_TX_P: KV2.5 TV2.16(TX+)
TX_N: KV2.2 KV3.2
TX_P: KV2.7 KV3.7
NetC45_1: C45.1 C47.1 C171.1 DD6.22(VDDIO) DD6.40(VDDIO) R70.2
NetC46_1: C46.1 C48.1 C170.1 DD6.7(VDDA_1.8) L2.1
NetC51_1: C51.1 DD6.42(VDDCO) L2.2 R64.1 R73.1
NetC52_2: C52.2 R73.2
NetC53_1: C53.1 R92.2 R93.2
NetC54_1: C54.1 R94.2 R95.2
NetC55_1: C55.1 R88.2 R89.2
NetC56_1: C56.1 R90.2 R91.2
NetC61_1: C61.1 KV1.1 KV2.1 KV3.1 KV4.1 R102.2 R103.2
NetC62_1: R98.1 R99.1 ; port MID_POINT_Eth1
NetC63_1: R100.1 R101.1 ; port MID_POINT_Eth2
NetC102_1: C102.1 R34.2 R322.1 VT17.1(B)
NetC122_1: C122.1 R268.1 R383.2
NetC124_1: C124.1 R269.1 R400.2
NetC125_1: C125.1 DD6.32(VDDC) R64.2
NetDD6_6: DD6.6(ISET) R65.1
NetDD6_28: DD6.28(SMRXD31) R233.1
NetDD6_29: DD6.29(SMRXD30) R234.1
NetDD6_30: DD6.30(SMRXC3) R51.1
NetDD6_33: DD6.33(SCOL3) R50.1
NetDD6_34: DD6.34(SCRS3) R321.1
NetDD6_36: DD6.36(SCL_MDC) R270.1 R383.1
NetDD6_37: DD6.37(SDA_MDIO) R271.1 R400.1
NetDD6_39: DD6.39(SPISN) R67.2
NetDD6_48: DD6.48(FXSD1) R68.2
NetHL15_C: HL15.C R74.2
NetHL16_C: HL16.C R75.2
NetKV1_8: KV1.8 KV2.8 KV3.8 KV4.8 VD8.2(K) VT4.3(K)
NetL3_1: L3.1 R72.2
NetR96_1: R96.1 R97.1 VT4.1(B) VT17.3(K)
NetR98_2: R98.2 TV1.15(CT)
NetR99_2: R99.2 TV1.10(CT)
NetR100_2: R100.2 TV2.15(CT)
NetR101_2: R101.2 TV2.10(CT)

Not connected (* = marked no-connect by the designer): DD6 13(NC)* 15(X2)*; TV1 4 5 12 13; TV2 4 5 12 13; VD6 5*; VD7 5*

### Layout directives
differential pair: ETH1_RX_N, ETH1_RX_P, ETH1_TX_N, ETH1_TX_P, ETH2_RX_N, ETH2_RX_P, ETH2_TX_N, ETH2_TX_P, RD1_N, RD1_P, RD2_N, RD2_P, RX_N, RX_P, TD1_N, TD1_P, TD2_N, TD2_P, TV1_RX_N, TV1_RX_P, TV1_TX_N, TV1_TX_P, TV2_RX_N, TV2_RX_P, TV2_TX_N, TV2_TX_P, TX_N, TX_P
net class Ethernet: ETH1_RX_N, ETH1_RX_P, ETH1_TX_N, ETH1_TX_P, ETH2_RX_N, ETH2_RX_P, ETH2_TX_N, ETH2_TX_P, RX_N, RX_P, TV1_RX_N, TV1_RX_P, TV1_TX_N, TV1_TX_P, TV2_RX_N, TV2_RX_P, TV2_TX_N, TV2_TX_P, TX_N, TX_P

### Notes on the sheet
- Резисторы R268..R271 разместить как можно ближе к DD6
- (near R318) Разместить по одному вблизи выводов DD6
- Настройка режима порта 1 в полно- или полу- дуплекс (Полнодуплекс)
- Выключение выхода тактового сигнала
- Установка Х1 как вход 50МГц
- (near HL16) Настройка управления потоком порта 1 (определяется автопереговорами)
- Разместить вблизи DD6
- Настройка скорости порта 1 (100Mbs)
- Включение Auto Neg порта 2
- Настройка скорости порта 2 (100Mbs)
- Включение Auto Neg порта 1
- Настройка режима порта 2в полно- или полу- дуплекс (Полнодуплекс)
- Выбор последовательного интерфейса (Значение "11" устанавливает MIIM
- Настройка управления потоком порта 2 (определяется автопереговорами)

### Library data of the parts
C43 C46 C61 C102 C169-C173 = C0603
C44 C45 C47 C48 C50 C51 C53-C60 C122 C124-C126 = C0402
C52 = C0805
DD6 = KSZ8863RLLI: Integrated 3-Port 10/100 Managed Switch with PHYs
HL15 HL16 = HT19-2132SYGC: High Brigh Yellow-Green LED
KV1-KV4 = Hongfa HFD4/5-S (standard SMT): High Frequency / RF Relays 5VDC Non-latching Single coil gullwing
L2 L3 = L0603
R34 R49-R65 R67 R68 R70-R85 R88-R97 R102 R103 R233 R234 R268-R271 R318-R322 R383 R400 = R0402
R98-R101 = RC03
TV1 TV2 = PT61018PEL_TRC1188NLE: Pulse Transformer 1CT_1CT Lan 10/100 Base TX Transormer Module
VD6 VD7 = TPD4E001DCKR: as VD2 on sheet KMXX87C01_CPU
VD8 = BZV55C
VD20 = BAS716: Low-Leakage Diode
VT4 VT17 = BC817-25

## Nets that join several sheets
3.3V: KMXX87C01_Main (13 pins), KMXX87C01_CPU (51 pins), KMXX87C01_RS-485 (C5.2 DD9.1 DD9.7), KMXX87C01_Ethernet (26 pins)
5V: KMXX87C01_Main (C4.2 T3.1 XP7.3), KMXX87C01_CPU (R14.1), KMXX87C01_RS-485 (C9.1 DA1.1), KMXX87C01_Ethernet (R102.1)
GND: KMXX87C01_Main (18 pins), KMXX87C01_CPU (67 pins), KMXX87C01_RS-485 (6 pins), KMXX87C01_Ethernet (52 pins)
GND_RS: KMXX87C01_Main (R116.1), KMXX87C01_RS-485 (14 pins)
BAT: KMXX87C01_Main (XP7.8), KMXX87C01_CPU (C27.1 DD3.6)
ByPassMode: KMXX87C01_CPU (DD3.41), KMXX87C01_Ethernet (DD6.24 R49.1)
Connect: KMXX87C01_CPU (DD4.4 R31.2 R328.1 VD4.2), KMXX87C01_Ethernet (R96.2)
D1_N: KMXX87C01_Main (XS2.A7 XS2.B7), KMXX87C01_CPU (R380.1 VD2.4)
D1_P: KMXX87C01_Main (XS2.A6 XS2.B6), KMXX87C01_CPU (R381.1 VD2.6)
ETH1_RX_N: KMXX87C01_Main (XS3.2), KMXX87C01_Ethernet (KV1.3)
ETH1_RX_P: KMXX87C01_Main (XS3.1), KMXX87C01_Ethernet (KV1.6)
ETH1_TX_N: KMXX87C01_Main (XS3.6), KMXX87C01_Ethernet (KV3.3)
ETH1_TX_P: KMXX87C01_Main (XS3.3), KMXX87C01_Ethernet (KV3.6)
ETH2_RX_N: KMXX87C01_Main (XS4.2), KMXX87C01_Ethernet (KV4.3)
ETH2_RX_P: KMXX87C01_Main (XS4.1), KMXX87C01_Ethernet (KV4.6)
ETH2_TX_N: KMXX87C01_Main (XS4.6), KMXX87C01_Ethernet (KV2.3)
ETH2_TX_P: KMXX87C01_Main (XS4.3), KMXX87C01_Ethernet (KV2.6)
ETH_RELEY_RST: KMXX87C01_CPU (DD3.7), KMXX87C01_Ethernet (R34.1)
ETH_RST: KMXX87C01_CPU (R32.1 VD4.1), KMXX87C01_Ethernet (C50.1 DD6.47 R71.1 VD20.1)
I2C_SCL: KMXX87C01_Main (T6.1 XP3.10), KMXX87C01_CPU (DD3.92), KMXX87C01_Ethernet (R268.2)
I2C_SDA: KMXX87C01_Main (T5.1 XP3.12), KMXX87C01_CPU (DD3.93), KMXX87C01_Ethernet (C126.1 R269.2)
INTRN: KMXX87C01_CPU (DD3.26 R29.1), KMXX87C01_Ethernet (DD6.35)
JTCK-SWCLK: KMXX87C01_Main (XS1.6), KMXX87C01_CPU (DD3.76 R7.2)
JTDI: KMXX87C01_Main (XS1.4), KMXX87C01_CPU (DD3.77)
JTDO/SWO: KMXX87C01_Main (XS1.8), KMXX87C01_CPU (DD3.89)
JTMS-SWDIO: KMXX87C01_Main (XS1.5), KMXX87C01_CPU (DD3.72)
MDC: KMXX87C01_CPU (DD3.16 R12.1), KMXX87C01_Ethernet (R270.2)
MDIO: KMXX87C01_CPU (DD3.25 R11.1), KMXX87C01_Ethernet (R271.2)
NetC62_1: KMXX87C01_Main (C62.1 R25.1 R40.1), KMXX87C01_Ethernet (R98.1 R99.1)
NetC63_1: KMXX87C01_Main (C63.1 R106.1 R107.1), KMXX87C01_Ethernet (R100.1 R101.1)
NJTRST: KMXX87C01_Main (XS1.3), KMXX87C01_CPU (C72.2 DD3.90 R39.1)
OTG_FS_VBUS: KMXX87C01_Main (XP7.4), KMXX87C01_CPU (DD3.68 R8.2 R325.2)
P1_Link_LED: KMXX87C01_Main (R43.1 R69.1), KMXX87C01_Ethernet (DD6.44 R74.1 R77.2 R81.2)
P2_Link_LED: KMXX87C01_Main (R109.1 R111.1), KMXX87C01_Ethernet (DD6.46 R75.1 R78.2 R82.2)
PA0: KMXX87C01_Main (XP6.4), KMXX87C01_CPU (DD3.23)
PA5: KMXX87C01_Main (XP6.5), KMXX87C01_CPU (DD3.30)
PA6: KMXX87C01_Main (XP6.6), KMXX87C01_CPU (DD3.31)
PA8: KMXX87C01_Main (XP7.7), KMXX87C01_CPU (DD3.67)
PB0: KMXX87C01_Main (XP7.9), KMXX87C01_CPU (DD3.35)
PB1: KMXX87C01_Main (XP3.7), KMXX87C01_CPU (DD3.36)
PB5: KMXX87C01_Main (XP6.7), KMXX87C01_CPU (DD3.91)
PB8: KMXX87C01_Main (XP6.8), KMXX87C01_CPU (DD3.95)
PB9: KMXX87C01_Main (XP6.10), KMXX87C01_CPU (DD3.96)
PB14: KMXX87C01_Main (XP6.11), KMXX87C01_CPU (DD3.53)
PB15: KMXX87C01_Main (XP6.12), KMXX87C01_CPU (DD3.54)
PC6: KMXX87C01_Main (XP6.13), KMXX87C01_CPU (DD3.63)
PC7: KMXX87C01_Main (XP6.14), KMXX87C01_CPU (DD3.64)
PC8: KMXX87C01_Main (XP6.15), KMXX87C01_CPU (DD3.65)
PD0: KMXX87C01_Main (XP3.9), KMXX87C01_CPU (DD3.81)
PD2: KMXX87C01_Main (XP3.3), KMXX87C01_CPU (DD3.83)
PD3: KMXX87C01_Main (XP3.5), KMXX87C01_CPU (DD3.84)
PD7: KMXX87C01_Main (XP6.16), KMXX87C01_CPU (DD3.88)
PD8: KMXX87C01_Main (XP3.14), KMXX87C01_CPU (DD3.55)
PD9: KMXX87C01_Main (XP3.1), KMXX87C01_CPU (DD3.56)
PD10: KMXX87C01_Main (XP3.11), KMXX87C01_CPU (DD3.57)
PD11: KMXX87C01_Main (XP3.15), KMXX87C01_CPU (DD3.58)
PD12: KMXX87C01_Main (XP7.10), KMXX87C01_CPU (DD3.59)
PD13: KMXX87C01_Main (XP7.12), KMXX87C01_CPU (DD3.60)
PD14: KMXX87C01_Main (XP3.16), KMXX87C01_CPU (DD3.61)
PD15: KMXX87C01_Main (XP4.2), KMXX87C01_CPU (DD3.62)
PE0: KMXX87C01_Main (XP4.11), KMXX87C01_CPU (DD3.97)
PE1: KMXX87C01_Main (XP4.5), KMXX87C01_CPU (DD3.98)
PE2: KMXX87C01_Main (XP4.6), KMXX87C01_CPU (DD3.1)
PE3: KMXX87C01_Main (XP4.9), KMXX87C01_CPU (DD3.2)
PE4: KMXX87C01_Main (XP4.3), KMXX87C01_CPU (DD3.3)
PE5: KMXX87C01_Main (XP7.11), KMXX87C01_CPU (DD3.4)
PE6: KMXX87C01_Main (XP4.10), KMXX87C01_CPU (DD3.5)
PE7: KMXX87C01_Main (XP4.4), KMXX87C01_CPU (DD3.38)
PE9: KMXX87C01_Main (XP6.2), KMXX87C01_CPU (DD3.40)
PE11: KMXX87C01_Main (XP6.1), KMXX87C01_CPU (DD3.42)
PE13: KMXX87C01_Main (XP4.1), KMXX87C01_CPU (DD3.44)
PE14: KMXX87C01_Main (XP4.8), KMXX87C01_CPU (DD3.45)
~{RESET}: KMXX87C01_Main (XS1.9), KMXX87C01_CPU (R35.2 R48.1)
RMII_CLK: KMXX87C01_CPU (DD3.24 R27.1 R317.2 R358.1), KMXX87C01_Ethernet (DD6.14 DD6.23)
RMII_CRS_DV: KMXX87C01_CPU (DD3.32), KMXX87C01_Ethernet (DD6.25 R54.1 R55.1)
RMII_RXD0: KMXX87C01_CPU (DD3.33), KMXX87C01_Ethernet (R62.1 R63.1 R234.2)
RMII_RXD1: KMXX87C01_CPU (DD3.34), KMXX87C01_Ethernet (R60.1 R61.1 R233.2)
RMII_TX_EN: KMXX87C01_CPU (R200.2), KMXX87C01_Ethernet (DD6.16 R320.1)
RMII_TXD0: KMXX87C01_CPU (R201.2), KMXX87C01_Ethernet (DD6.20 R318.1)
RMII_TXD1: KMXX87C01_CPU (R202.2), KMXX87C01_Ethernet (DD6.19 R319.1)
RS485_N: KMXX87C01_Main (XT2.3), KMXX87C01_RS-485 (C64.2 R18.1 VD3.2)
RS485_P: KMXX87C01_Main (XT2.1), KMXX87C01_RS-485 (C65.2 R26.1 VD3.1)
RS485_RTS: KMXX87C01_CPU (DD3.85), KMXX87C01_RS-485 (R4.1)
RS485_RX: KMXX87C01_CPU (DD3.87), KMXX87C01_RS-485 (R6.1)
RS485_TX: KMXX87C01_CPU (DD3.86), KMXX87C01_RS-485 (R5.1)
Speed_Conf_P1: KMXX87C01_Main (R87.1 R105.1), KMXX87C01_Ethernet (DD6.43 R84.2 R85.1)
Speed_Conf_P2: KMXX87C01_Main (R113.1 R115.1), KMXX87C01_Ethernet (DD6.27 R58.2 R59.1)
SPI3_MISO: KMXX87C01_Main (XP3.4), KMXX87C01_CPU (DD3.79)
SPI3_MOSI: KMXX87C01_Main (XP3.2), KMXX87C01_CPU (DD3.80)
SPI3_SCK: KMXX87C01_Main (XP3.6), KMXX87C01_CPU (DD3.78)
VBUS: KMXX87C01_Main (XS2.A4_B9 XS2.B4_A9), KMXX87C01_CPU (C73.2 L8.1 VD2.5)

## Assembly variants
KMXX87C01: not fitted BQ2 C5 C9 C10 C11 C31 C38 C39 C49 C64 C65 C66 C75 C76 C122 C124 C126 C169 C170 C171 C172 C173 DA1 DA2 DD9 HL15 HL16 L4 L5 L6 R4 R5 R6 R15 R17 R18 R26 R30 R43 R47 R48 R52 R55 R59 R61 R62 R66 R74 R75 R77 R78 R79 R80 R85 R87 R103 R104 R109 R110 R113 R114 R116 R167 R268 R269 R317 R326 R328 R329 R383 R400 VD1 VD3 VD4 VD20 XP2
